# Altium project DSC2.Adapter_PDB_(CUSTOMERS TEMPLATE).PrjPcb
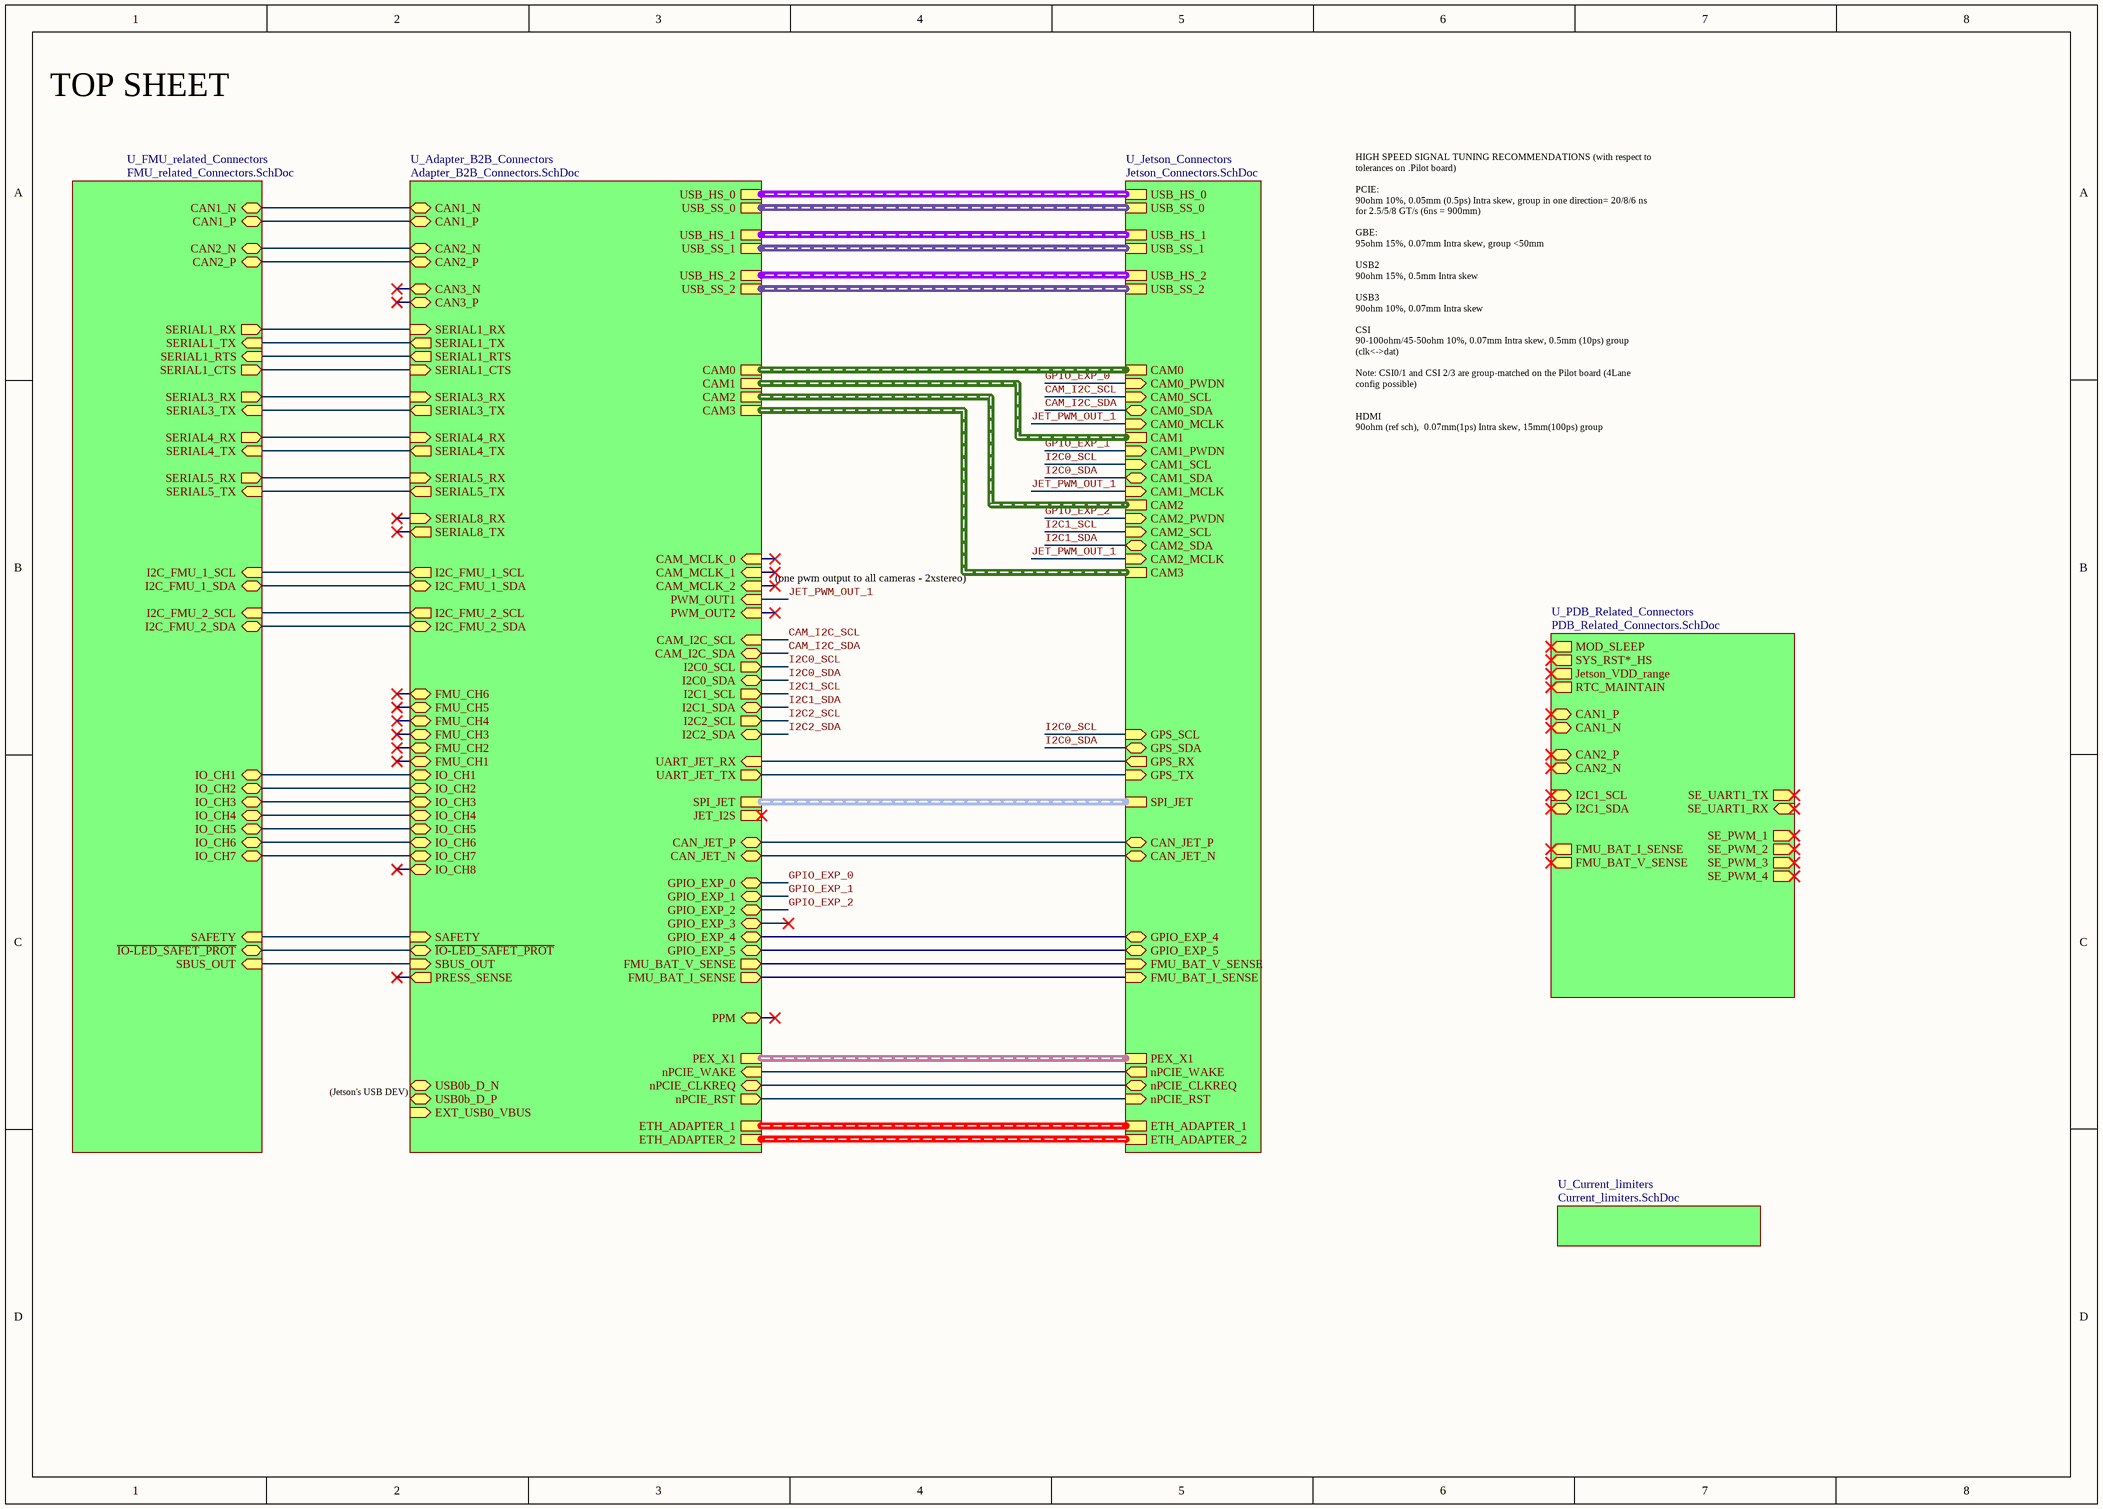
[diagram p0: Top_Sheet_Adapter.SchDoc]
CAGE_CODE: ?????; CONTRACT_NUMBER: <CONTRACT NO>; DOC_NO_ASSY_DWG: <ASSY DWG NO>; DOC_NO_BOM: <BOM DOC NO>; DOC_NO_FAB_DWG: <FAB DWG NO>; DOC_NO_SCH_DWG: <SCH DWG NO>; gDesigner: Ján Parilla; gProjectName: DCS2.Adapter_Template; gRevision: rev.0; gSheetTotal: 3; gYear: 2023; PCB_2_DEC_TOL: +/-.01; PCB_3_DEC_TOL: +/-.010; PCB_ANG_TOL: +/-1/2; PCB_ASSEMBLY_NO: <PCB ASSY NO>; PCB_CHECKER: - -----; PCB_CHECKER_APP_DATE: --/--/----; PCB_DESIGNER: - -----; PCB_DESIGNER_APP_DATE: --/--/----; PCB_DWG_NO: <PCB DWG NO>; PCB_ENGINEER: - -----; PCB_ENGINEER_APP_DATE: --/--/----; PCB_PART_NUMBER: <PCB PN>; PCB_REV: A; SCH_REV: A
7 sheets, 50 parts. Net scope: hierarchical (ports join the sheet entries above them; power ports are global).
Board file: DCS_nano_Adapter_PDB_Template.PcbDoc
Sheets:
  Top_Sheet_Adapter.SchDoc
    U_Adapter_B2B_Connectors = Adapter_B2B_Connectors.SchDoc
    U_Jetson_Connectors = Jetson_Connectors.SchDoc
    U_FMU_related_Connectors = FMU_related_Connectors.SchDoc
    U_PDB_Related_Connectors = PDB_Related_Connectors.SchDoc
    U_Current_limiters = Current_limiters.SchDoc
  DCDC_Regulators.SchDoc

## Sheet Top_Sheet_Adapter.SchDoc
size A3; SheetNumber: 1; SheetTotal: 7

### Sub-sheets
U_Adapter_B2B_Connectors = Adapter_B2B_Connectors.SchDoc: ETH_ADAPTER_1 (harness ETH_GB), CAN_JET_P (bidir), CAN_JET_N (bidir), CAN2_N (bidir), CAN2_P (bidir), CAN1_N (bidir), CAN1_P (bidir), CAN3_N (bidir), CAN3_P (bidir), SERIAL5_RX (in), SERIAL5_TX (out), SERIAL4_RX (in), SERIAL4_TX (out), SERIAL3_RX (in), SERIAL3_TX (out), SERIAL1_TX (out), SERIAL1_RX (in), SERIAL1_CTS (in), SERIAL1_RTS (out), SERIAL8_TX (out), SERIAL8_RX (in), GPIO_EXP_1 (bidir), GPIO_EXP_2 (bidir), GPIO_EXP_0 (bidir), GPIO_EXP_3 (bidir), GPIO_EXP_4 (bidir), GPIO_EXP_5 (bidir), ETH_ADAPTER_2 (harness ETH_GB), I2C_FMU_1_SCL (out), I2C_FMU_1_SDA (bidir), I2C_FMU_2_SCL (out), I2C_FMU_2_SDA (bidir), PRESS_SENSE (out), ~{IO-LED_SAFET_PROT} (bidir), SBUS_OUT (in), SAFETY (in), FMU_CH6 (bidir), FMU_CH5 (bidir), FMU_CH4 (bidir), FMU_CH3 (bidir), FMU_CH2 (bidir), FMU_CH1 (bidir), IO_CH1 (bidir), IO_CH2 (bidir), IO_CH3 (bidir), IO_CH4 (bidir), IO_CH5 (bidir), IO_CH6 (bidir), IO_CH7 (bidir), IO_CH8 (bidir), nPCIE_CLKREQ (bidir), nPCIE_RST (out), nPCIE_WAKE (in), UART_JET_TX (out), UART_JET_RX (in), SPI_JET (harness SPI), PWM_OUT1 (in), PWM_OUT2 (in), CAM0 (harness CSIx2), CAM2 (harness CSIx2), CAM_I2C_SCL (in), CAM_I2C_SDA (bidir), CAM_MCLK_1 (in), CAM_MCLK_2 (in), I2C0_SCL (out), I2C0_SDA (bidir), I2C1_SCL (out), I2C1_SDA (bidir), I2C2_SCL (out), I2C2_SDA (bidir), USB_SS_2 (harness USB3), USB_SS_1 (harness USB3), USB_SS_0 (harness USB3), CAM1 (harness CSIx2), CAM3 (harness CSIx2), CAM_MCLK_0 (in), USB_HS_1 (harness USB2), USB_HS_2 (harness USB2), PEX_X1 (harness PEX_x1), USB_HS_0 (harness USB2), JET_I2S (harness I2S), FMU_BAT_V_SENSE (out), FMU_BAT_I_SENSE (out), PPM (bidir), USB0b_D_N (bidir), USB0b_D_P (bidir), EXT_USB0_VBUS (in)
U_Current_limiters = Current_limiters.SchDoc: no entries
U_FMU_related_Connectors = FMU_related_Connectors.SchDoc: CAN2_N (bidir), CAN2_P (bidir), CAN1_N (bidir), CAN1_P (bidir), SERIAL5_RX (out), SERIAL5_TX (in), SERIAL4_RX (out), SERIAL4_TX (in), SERIAL3_RX (out), SERIAL3_TX (in), SERIAL1_TX (in), SERIAL1_RX (out), SERIAL1_CTS (out), SERIAL1_RTS (in), I2C_FMU_1_SCL (in), I2C_FMU_1_SDA (bidir), I2C_FMU_2_SCL (in), I2C_FMU_2_SDA (bidir), ~{IO-LED_SAFET_PROT} (bidir), SBUS_OUT (in), SAFETY (in), IO_CH1 (bidir), IO_CH2 (bidir), IO_CH3 (bidir), IO_CH4 (bidir), IO_CH5 (bidir), IO_CH6 (bidir), IO_CH7 (bidir)
U_Jetson_Connectors = Jetson_Connectors.SchDoc: CAN_JET_P (bidir), CAN_JET_N (bidir), GPS_TX (in), GPS_RX (out), SPI_JET (harness SPI), CAM0 (harness CSIx2), CAM2 (harness CSIx2), CAM1 (harness CSIx2), CAM3 (harness CSIx2), CAM0_PWDN (in), CAM1_PWDN (in), CAM2_PWDN (in), CAM0_SCL (in), CAM0_SDA (bidir), CAM1_SCL (in), CAM1_SDA (bidir), CAM2_SCL (in), CAM2_SDA (bidir), CAM0_MCLK (in), CAM1_MCLK (in), CAM2_MCLK (in), GPS_SCL (in), GPS_SDA (bidir), ETH_ADAPTER_1 (harness ETH_GB), ETH_ADAPTER_2 (harness ETH_GB), nPCIE_CLKREQ (bidir), nPCIE_RST (in), nPCIE_WAKE (out), PEX_X1 (harness PEX_x1), GPIO_EXP_4 (bidir), GPIO_EXP_5 (bidir), FMU_BAT_V_SENSE (in), FMU_BAT_I_SENSE (in), USB_SS_0 (harness USB3), USB_HS_0 (harness USB2), USB_SS_1 (harness USB3), USB_HS_1 (harness USB2), USB_SS_2 (harness USB3), USB_HS_2 (harness USB2)
U_PDB_Related_Connectors = PDB_Related_Connectors.SchDoc: I2C1_SCL (in), I2C1_SDA (bidir), MOD_SLEEP (out), SYS_RST*_HS (out), Jetson_VDD_range (out), CAN2_P (bidir), CAN2_N (bidir), SE_UART1_TX (out), CAN1_P (bidir), CAN1_N (bidir), SE_UART1_RX (in), SE_PWM_1 (out), SE_PWM_2 (out), SE_PWM_3 (out), SE_PWM_4 (out), RTC_MAINTAIN (out), FMU_BAT_I_SENSE (out), FMU_BAT_V_SENSE (out)

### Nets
CAM_I2C_SCL: sheet U_Adapter_B2B_Connectors/CAM_I2C_SCL, sheet U_Jetson_Connectors/CAM0_SCL
CAM_I2C_SDA: sheet U_Adapter_B2B_Connectors/CAM_I2C_SDA, sheet U_Jetson_Connectors/CAM0_SDA
CAN_1_N: sheet U_Adapter_B2B_Connectors/CAN1_N, sheet U_FMU_related_Connectors/CAN1_N
CAN_1_P: sheet U_Adapter_B2B_Connectors/CAN1_P, sheet U_FMU_related_Connectors/CAN1_P
CAN_2_N: sheet U_Adapter_B2B_Connectors/CAN2_N, sheet U_FMU_related_Connectors/CAN2_N
CAN_2_P: sheet U_Adapter_B2B_Connectors/CAN2_P, sheet U_FMU_related_Connectors/CAN2_P
CAN_JET_N: sheet U_Adapter_B2B_Connectors/CAN_JET_N, sheet U_Jetson_Connectors/CAN_JET_N
CAN_JET_P: sheet U_Adapter_B2B_Connectors/CAN_JET_P, sheet U_Jetson_Connectors/CAN_JET_P
FMU_BAT_I_SENSE: sheet U_Adapter_B2B_Connectors/FMU_BAT_I_SENSE, sheet U_Jetson_Connectors/FMU_BAT_I_SENSE
FMU_BAT_V_SENSE: sheet U_Adapter_B2B_Connectors/FMU_BAT_V_SENSE, sheet U_Jetson_Connectors/FMU_BAT_V_SENSE
FMU_SAFETY_SIG: sheet U_Adapter_B2B_Connectors/SAFETY, sheet U_FMU_related_Connectors/SAFETY
GPIO_EXP_0: sheet U_Adapter_B2B_Connectors/GPIO_EXP_0, sheet U_Jetson_Connectors/CAM0_PWDN
GPIO_EXP_1: sheet U_Adapter_B2B_Connectors/GPIO_EXP_1, sheet U_Jetson_Connectors/CAM1_PWDN
GPIO_EXP_2: sheet U_Adapter_B2B_Connectors/GPIO_EXP_2, sheet U_Jetson_Connectors/CAM2_PWDN
GPIO_EXP_4: sheet U_Adapter_B2B_Connectors/GPIO_EXP_4, sheet U_Jetson_Connectors/GPIO_EXP_4
GPIO_EXP_5: sheet U_Adapter_B2B_Connectors/GPIO_EXP_5, sheet U_Jetson_Connectors/GPIO_EXP_5
I2C0_SCL: sheet U_Adapter_B2B_Connectors/I2C0_SCL, sheet U_Jetson_Connectors/CAM1_SCL, sheet U_Jetson_Connectors/GPS_SCL
I2C0_SDA: sheet U_Adapter_B2B_Connectors/I2C0_SDA, sheet U_Jetson_Connectors/CAM1_SDA, sheet U_Jetson_Connectors/GPS_SDA
I2C1_SCL: sheet U_Adapter_B2B_Connectors/I2C1_SCL, sheet U_Jetson_Connectors/CAM2_SCL
I2C1_SDA: sheet U_Adapter_B2B_Connectors/I2C1_SDA, sheet U_Jetson_Connectors/CAM2_SDA
I2C_FMU_1_SCL: sheet U_Adapter_B2B_Connectors/I2C_FMU_1_SCL, sheet U_FMU_related_Connectors/I2C_FMU_1_SCL
I2C_FMU_1_SDA: sheet U_Adapter_B2B_Connectors/I2C_FMU_1_SDA, sheet U_FMU_related_Connectors/I2C_FMU_1_SDA
I2C_FMU_2_SCL: sheet U_Adapter_B2B_Connectors/I2C_FMU_2_SCL, sheet U_FMU_related_Connectors/I2C_FMU_2_SCL
I2C_FMU_2_SDA: sheet U_Adapter_B2B_Connectors/I2C_FMU_2_SDA, sheet U_FMU_related_Connectors/I2C_FMU_2_SDA
~{IO-LED_SAFET_PROT}: sheet U_Adapter_B2B_Connectors/~{IO-LED_SAFET_PROT}, sheet U_FMU_related_Connectors/~{IO-LED_SAFET_PROT}
IO_CH1: sheet U_Adapter_B2B_Connectors/IO_CH1, sheet U_FMU_related_Connectors/IO_CH1
IO_CH2: sheet U_Adapter_B2B_Connectors/IO_CH2, sheet U_FMU_related_Connectors/IO_CH2
IO_CH3: sheet U_Adapter_B2B_Connectors/IO_CH3, sheet U_FMU_related_Connectors/IO_CH3
IO_CH4: sheet U_Adapter_B2B_Connectors/IO_CH4, sheet U_FMU_related_Connectors/IO_CH4
IO_CH5: sheet U_Adapter_B2B_Connectors/IO_CH5, sheet U_FMU_related_Connectors/IO_CH5
IO_CH6: sheet U_Adapter_B2B_Connectors/IO_CH6, sheet U_FMU_related_Connectors/IO_CH6
IO_CH7: sheet U_Adapter_B2B_Connectors/IO_CH7, sheet U_FMU_related_Connectors/IO_CH7
JET_PWM_OUT_1: sheet U_Adapter_B2B_Connectors/PWM_OUT1, sheet U_Jetson_Connectors/CAM0_MCLK, sheet U_Jetson_Connectors/CAM1_MCLK, sheet U_Jetson_Connectors/CAM2_MCLK
nPCIE_CLKREQ: sheet U_Adapter_B2B_Connectors/nPCIE_CLKREQ, sheet U_Jetson_Connectors/nPCIE_CLKREQ
nPCIE_RST: sheet U_Adapter_B2B_Connectors/nPCIE_RST, sheet U_Jetson_Connectors/nPCIE_RST
nPCIE_WAKE: sheet U_Adapter_B2B_Connectors/nPCIE_WAKE, sheet U_Jetson_Connectors/nPCIE_WAKE
SBUS_OUT: sheet U_Adapter_B2B_Connectors/SBUS_OUT, sheet U_FMU_related_Connectors/SBUS_OUT
SERIAL1_CTS: sheet U_Adapter_B2B_Connectors/SERIAL1_CTS, sheet U_FMU_related_Connectors/SERIAL1_CTS
SERIAL1_RTS: sheet U_Adapter_B2B_Connectors/SERIAL1_RTS, sheet U_FMU_related_Connectors/SERIAL1_RTS
SERIAL1_RX: sheet U_Adapter_B2B_Connectors/SERIAL1_RX, sheet U_FMU_related_Connectors/SERIAL1_RX
SERIAL1_TX: sheet U_Adapter_B2B_Connectors/SERIAL1_TX, sheet U_FMU_related_Connectors/SERIAL1_TX
SERIAL3_RX: sheet U_Adapter_B2B_Connectors/SERIAL3_RX, sheet U_FMU_related_Connectors/SERIAL3_RX
SERIAL3_TX: sheet U_Adapter_B2B_Connectors/SERIAL3_TX, sheet U_FMU_related_Connectors/SERIAL3_TX
SERIAL4_RX: sheet U_Adapter_B2B_Connectors/SERIAL4_RX, sheet U_FMU_related_Connectors/SERIAL4_RX
SERIAL4_TX: sheet U_Adapter_B2B_Connectors/SERIAL4_TX, sheet U_FMU_related_Connectors/SERIAL4_TX
SERIAL5_RX: sheet U_Adapter_B2B_Connectors/SERIAL5_RX, sheet U_FMU_related_Connectors/SERIAL5_RX
SERIAL5_TX: sheet U_Adapter_B2B_Connectors/SERIAL5_TX, sheet U_FMU_related_Connectors/SERIAL5_TX
UART_JET_RX: sheet U_Adapter_B2B_Connectors/UART_JET_RX, sheet U_Jetson_Connectors/GPS_RX
UART_JET_TX: sheet U_Adapter_B2B_Connectors/UART_JET_TX, sheet U_Jetson_Connectors/GPS_TX

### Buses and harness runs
harness sheet U_Adapter_B2B_Connectors/CAM0 = sheet U_Jetson_Connectors/CAM0
harness sheet U_Adapter_B2B_Connectors/CAM1 = sheet U_Jetson_Connectors/CAM1
harness sheet U_Adapter_B2B_Connectors/CAM2 = sheet U_Jetson_Connectors/CAM2
harness sheet U_Adapter_B2B_Connectors/CAM3 = sheet U_Jetson_Connectors/CAM3
harness sheet U_Adapter_B2B_Connectors/ETH_ADAPTER_1 = sheet U_Jetson_Connectors/ETH_ADAPTER_1
harness sheet U_Adapter_B2B_Connectors/ETH_ADAPTER_2 = sheet U_Jetson_Connectors/ETH_ADAPTER_2
harness sheet U_Adapter_B2B_Connectors/PEX_X1 = sheet U_Jetson_Connectors/PEX_X1
harness sheet U_Adapter_B2B_Connectors/SPI_JET = sheet U_Jetson_Connectors/SPI_JET
harness sheet U_Adapter_B2B_Connectors/USB_HS_0 = sheet U_Jetson_Connectors/USB_HS_0
harness sheet U_Adapter_B2B_Connectors/USB_HS_1 = sheet U_Jetson_Connectors/USB_HS_1
harness sheet U_Adapter_B2B_Connectors/USB_HS_2 = sheet U_Jetson_Connectors/USB_HS_2
harness sheet U_Adapter_B2B_Connectors/USB_SS_0 = sheet U_Jetson_Connectors/USB_SS_0
harness sheet U_Adapter_B2B_Connectors/USB_SS_1 = sheet U_Jetson_Connectors/USB_SS_1
harness sheet U_Adapter_B2B_Connectors/USB_SS_2 = sheet U_Jetson_Connectors/USB_SS_2

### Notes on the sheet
- TOP SHEET
- HIGH SPEED SIGNAL TUNING RECOMMENDATIONS (with respect to tolerances on .Pilot board)
  PCIE:
  90ohm 10%, 0.05mm (0.5ps) Intra skew, group in one direction= 20/8/6 ns for 2.5/5/8 GT/s (6ns = 900mm)
  GBE:
  95ohm 15%, 0.07mm Intra skew, group <50mm
  USB2
  90ohm 15%, 0.5mm Intra skew
  USB3
  90ohm 10%, 0.07mm Intra skew
  CSI
  90-100ohm/45-50ohm 10%, 0.07mm Intra skew, 0.5mm (10ps) group (clk<->dat)
  Note: CSI0/1 and CSI 2/3 are group-matched on the Pilot board (4Lane config possible)
  HDMI
  90ohm (ref sch),  0.07mm(1ps) Intra skew, 15mm(100ps) group
- (one pwm output to all cameras - 2xstereo)
- (Jetson's USB DEV)

## Sheet Adapter_B2B_Connectors.SchDoc
size A3; SheetNumber: 2; SheetTotal: 7
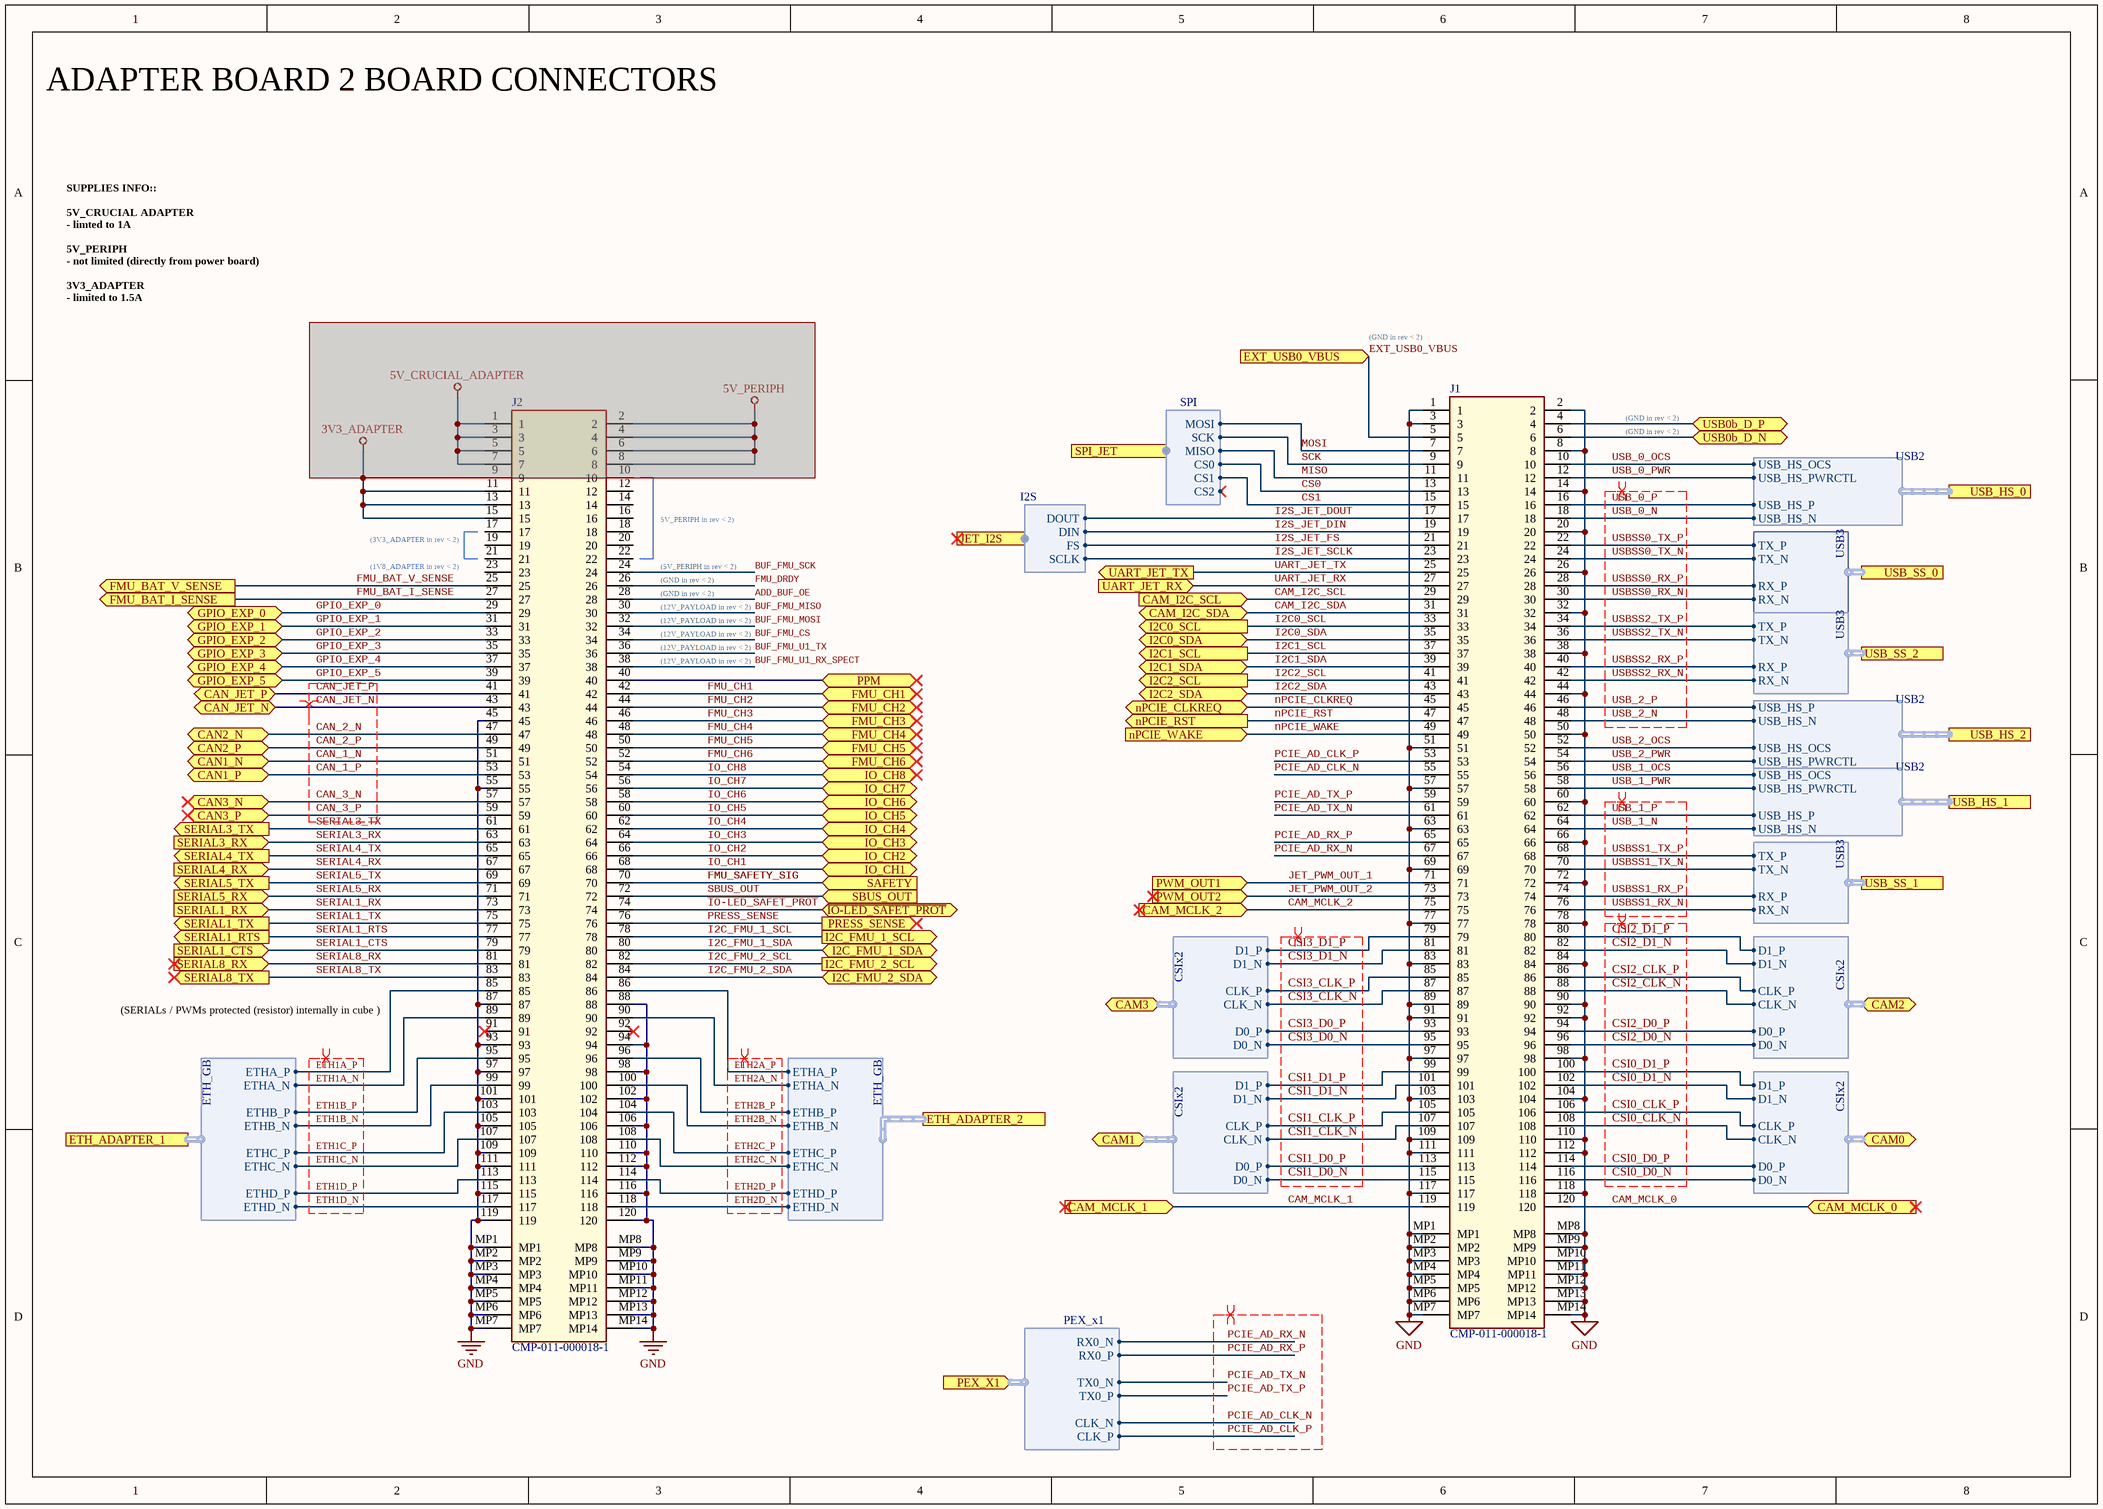
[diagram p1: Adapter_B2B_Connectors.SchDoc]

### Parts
J1  CMP-011-000018-1  [HRS_FX10A-120S/12-SV]
J2  CMP-011-000018-1  [HRS_FX10A-120S/12-SV]

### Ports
CAM0 (bidir, harness CSIx2), CAM1 (bidir, harness CSIx2), CAM2 (bidir, harness CSIx2), CAM3 (bidir, harness CSIx2), CAM_I2C_SCL (in), CAM_I2C_SDA (bidir), CAM_MCLK_0 (in), CAM_MCLK_1 (in), CAM_MCLK_2 (in), CAN1_N (bidir), CAN1_P (bidir), CAN2_N (bidir), CAN2_P (bidir), CAN3_N (bidir), CAN3_P (bidir), CAN_JET_N (bidir), CAN_JET_P (bidir), ETH_ADAPTER_1 (harness ETH_GB), ETH_ADAPTER_2 (harness ETH_GB), EXT_USB0_VBUS (in), FMU_BAT_I_SENSE (out), FMU_BAT_V_SENSE (out), FMU_CH1 (bidir), FMU_CH2 (bidir), FMU_CH3 (bidir), FMU_CH4 (bidir), FMU_CH5 (bidir), FMU_CH6 (bidir), GPIO_EXP_0 (bidir), GPIO_EXP_1 (bidir), GPIO_EXP_2 (bidir), GPIO_EXP_3 (bidir), GPIO_EXP_4 (bidir), GPIO_EXP_5 (bidir), I2C0_SCL (out), I2C0_SDA (bidir), I2C1_SCL (out), I2C1_SDA (bidir), I2C2_SCL (out), I2C2_SDA (bidir), I2C_FMU_1_SCL (out), I2C_FMU_1_SDA (bidir), I2C_FMU_2_SCL (out), I2C_FMU_2_SDA (bidir), IO_CH1 (bidir), IO_CH2 (bidir), IO_CH3 (bidir), IO_CH4 (bidir), IO_CH5 (bidir), IO_CH6 (bidir), IO_CH7 (bidir), IO_CH8 (bidir), JET_I2S (in, harness I2S), nPCIE_CLKREQ (bidir), nPCIE_RST (out), nPCIE_WAKE (in), PEX_X1 (in, harness PEX_x1), PPM (bidir), PRESS_SENSE (out), PWM_OUT1 (in), PWM_OUT2 (in), SAFETY (in), SBUS_OUT (in), SERIAL1_CTS (in), SERIAL1_RTS (out), SERIAL1_RX (in), SERIAL1_TX (out), SERIAL3_RX (in), SERIAL3_TX (out), SERIAL4_RX (in), SERIAL4_TX (out), SERIAL5_RX (in), SERIAL5_TX (out), SERIAL8_RX (in), SERIAL8_TX (out), SPI_JET (harness SPI), UART_JET_RX (in), UART_JET_TX (out), USB0b_D_N (bidir), USB0b_D_P (bidir), USB_HS_0 (harness USB2), USB_HS_1 (harness USB2), USB_HS_2 (harness USB2), USB_SS_0 (harness USB3), USB_SS_1 (harness USB3), USB_SS_2 (harness USB3), ~{IO-LED_SAFET_PROT} (bidir)

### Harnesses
ETH_GB: ETHB_N, ETHB_P, ETHA_P, ETHA_N, ETHD_N, ETHD_P, ETHC_P, ETHC_N
CSIx2: CLK_N, CLK_P, D0_N, D0_P, D1_N, D1_P
SPI: MOSI, MISO, SCK, CS0, CS1, CS2
USB3: RX_N, RX_P, TX_P, TX_N
PEX_x1: CLK_P, CLK_N, TX0_P, TX0_N, RX0_N, RX0_P
USB2: USB_HS_OCS, USB_HS_PWRCTL, USB_HS_P, USB_HS_N
I2S: DOUT, DIN, FS, SCLK

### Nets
GND: J1.1 J1.2 J1.3 J1.8 J1.14 J1.20 J1.26 J1.32 J1.38 J1.44 J1.50 J1.51 J1.57 J1.60 J1.63 J1.66 J1.69 J1.72 J1.77 J1.78 J1.83 J1.84 J1.89 J1.90 J1.91 J1.92 J1.97 J1.98 J1.103 J1.104 J1.109 J1.110 J1.111 J1.112 J1.117 J1.118 J1.MP1 J1.MP2 J1.MP3 J1.MP4 J1.MP5 J1.MP6 J1.MP7 J1.MP8 J1.MP9 J1.MP10 J1.MP11 J1.MP12 J1.MP13 J1.MP14 J2.45 J2.55 J2.87 J2.88 J2.93 J2.94 J2.97 J2.98 J2.101 J2.102 J2.105 J2.106 J2.109 J2.110 J2.111 J2.112 J2.115 J2.116 J2.119 J2.120 J2.MP1 J2.MP2 J2.MP3 J2.MP4 J2.MP5 J2.MP6 J2.MP7 J2.MP8 J2.MP9 J2.MP10 J2.MP11 J2.MP12 J2.MP13 J2.MP14
ADD_BUF_OE: J2.28
BUF_FMU_CS: J2.34
BUF_FMU_MISO: J2.30
BUF_FMU_MOSI: J2.32
BUF_FMU_SCK: J2.24
BUF_FMU_U1_RX_SPECT: J2.38
BUF_FMU_U1_TX: J2.36
CAM_I2C_SCL: J1.29 ; port CAM_I2C_SCL
CAM_I2C_SDA: J1.31 ; port CAM_I2C_SDA
CAM_MCLK_0: J1.120 ; port CAM_MCLK_0
CAM_MCLK_1: J1.119 ; port CAM_MCLK_1
CAM_MCLK_2: J1.75 ; port CAM_MCLK_2
CAN_1_N: J2.51 ; port CAN1_N
CAN_1_P: J2.53 ; port CAN1_P
CAN_2_N: J2.47 ; port CAN2_N
CAN_2_P: J2.49 ; port CAN2_P
CAN_3_N: J2.57 ; port CAN3_N
CAN_3_P: J2.59 ; port CAN3_P
CAN_JET_N: J2.43 ; port CAN_JET_N
CAN_JET_P: J2.41 ; port CAN_JET_P
CS0: J1.13 ; port SPI_JET.CS0
CS1: J1.15 ; port SPI_JET.CS1
CSI0_CLK_N: J1.108 ; port CAM0.CLK_N
CSI0_CLK_P: J1.106 ; port CAM0.CLK_P
CSI0_D0_N: J1.116 ; port CAM0.D0_N
CSI0_D0_P: J1.114 ; port CAM0.D0_P
CSI0_D1_N: J1.102 ; port CAM0.D1_N
CSI0_D1_P: J1.100 ; port CAM0.D1_P
CSI1_CLK_N: J1.107 ; port CAM1.CLK_N
CSI1_CLK_P: J1.105 ; port CAM1.CLK_P
CSI1_D0_N: J1.115 ; port CAM1.D0_N
CSI1_D0_P: J1.113 ; port CAM1.D0_P
CSI1_D1_N: J1.101 ; port CAM1.D1_N
CSI1_D1_P: J1.99 ; port CAM1.D1_P
CSI2_CLK_N: J1.88 ; port CAM2.CLK_N
CSI2_CLK_P: J1.86 ; port CAM2.CLK_P
CSI2_D0_N: J1.96 ; port CAM2.D0_N
CSI2_D0_P: J1.94 ; port CAM2.D0_P
CSI2_D1_N: J1.82 ; port CAM2.D1_N
CSI2_D1_P: J1.80 ; port CAM2.D1_P
CSI3_CLK_N: J1.87 ; port CAM3.CLK_N
CSI3_CLK_P: J1.85 ; port CAM3.CLK_P
CSI3_D0_N: J1.95 ; port CAM3.D0_N
CSI3_D0_P: J1.93 ; port CAM3.D0_P
CSI3_D1_N: J1.81 ; port CAM3.D1_N
CSI3_D1_P: J1.79 ; port CAM3.D1_P
ETH1A_N: J2.89 ; port ETH_ADAPTER_1.ETHA_N
ETH1A_P: J2.85 ; port ETH_ADAPTER_1.ETHA_P
ETH1B_N: J2.99 ; port ETH_ADAPTER_1.ETHB_N
ETH1B_P: J2.95 ; port ETH_ADAPTER_1.ETHB_P
ETH1C_N: J2.107 ; port ETH_ADAPTER_1.ETHC_N
ETH1C_P: J2.103 ; port ETH_ADAPTER_1.ETHC_P
ETH1D_N: J2.117 ; port ETH_ADAPTER_1.ETHD_N
ETH1D_P: J2.113 ; port ETH_ADAPTER_1.ETHD_P
ETH2A_N: J2.90 ; port ETH_ADAPTER_2.ETHA_N
ETH2A_P: J2.86 ; port ETH_ADAPTER_2.ETHA_P
ETH2B_N: J2.100 ; port ETH_ADAPTER_2.ETHB_N
ETH2B_P: J2.96 ; port ETH_ADAPTER_2.ETHB_P
ETH2C_N: J2.108 ; port ETH_ADAPTER_2.ETHC_N
ETH2C_P: J2.104 ; port ETH_ADAPTER_2.ETHC_P
ETH2D_N: J2.118 ; port ETH_ADAPTER_2.ETHD_N
ETH2D_P: J2.114 ; port ETH_ADAPTER_2.ETHD_P
EXT_USB0_VBUS: J1.5 ; port EXT_USB0_VBUS
FMU_BAT_I_SENSE: J2.27 ; port FMU_BAT_I_SENSE
FMU_BAT_V_SENSE: J2.25 ; port FMU_BAT_V_SENSE
FMU_CH1: J2.42 ; port FMU_CH1
FMU_CH2: J2.44 ; port FMU_CH2
FMU_CH3: J2.46 ; port FMU_CH3
FMU_CH4: J2.48 ; port FMU_CH4
FMU_CH5: J2.50 ; port FMU_CH5
FMU_CH6: J2.52 ; port FMU_CH6
FMU_DRDY: J2.26
FMU_SAFETY_SIG: J2.70 ; port SAFETY
GPIO_EXP_0: J2.29 ; port GPIO_EXP_0
GPIO_EXP_1: J2.31 ; port GPIO_EXP_1
GPIO_EXP_2: J2.33 ; port GPIO_EXP_2
GPIO_EXP_3: J2.35 ; port GPIO_EXP_3
GPIO_EXP_4: J2.37 ; port GPIO_EXP_4
GPIO_EXP_5: J2.39 ; port GPIO_EXP_5
I2C0_SCL: J1.33 ; port I2C0_SCL
I2C0_SDA: J1.35 ; port I2C0_SDA
I2C1_SCL: J1.37 ; port I2C1_SCL
I2C1_SDA: J1.39 ; port I2C1_SDA
I2C2_SCL: J1.41 ; port I2C2_SCL
I2C2_SDA: J1.43 ; port I2C2_SDA
I2C_FMU_1_SCL: J2.78 ; port I2C_FMU_1_SCL
I2C_FMU_1_SDA: J2.80 ; port I2C_FMU_1_SDA
I2C_FMU_2_SCL: J2.82 ; port I2C_FMU_2_SCL
I2C_FMU_2_SDA: J2.84 ; port I2C_FMU_2_SDA
I2S_JET_DIN: J1.19 ; port JET_I2S.DIN
I2S_JET_DOUT: J1.17 ; port JET_I2S.DOUT
I2S_JET_FS: J1.21 ; port JET_I2S.FS
I2S_JET_SCLK: J1.23 ; port JET_I2S.SCLK
~{IO-LED_SAFET_PROT}: J2.74 ; port ~{IO-LED_SAFET_PROT}
IO_CH1: J2.68 ; port IO_CH1
IO_CH2: J2.66 ; port IO_CH2
IO_CH3: J2.64 ; port IO_CH3
IO_CH4: J2.62 ; port IO_CH4
IO_CH5: J2.60 ; port IO_CH5
IO_CH6: J2.58 ; port IO_CH6
IO_CH7: J2.56 ; port IO_CH7
IO_CH8: J2.54 ; port IO_CH8
JET_PWM_OUT_1: J1.71 ; port PWM_OUT1
JET_PWM_OUT_2: J1.73 ; port PWM_OUT2
MISO: J1.11 ; port SPI_JET.MISO
MOSI: J1.7 ; port SPI_JET.MOSI
nPCIE_CLKREQ: J1.45 ; port nPCIE_CLKREQ
nPCIE_RST: J1.47 ; port nPCIE_RST
nPCIE_WAKE: J1.49 ; port nPCIE_WAKE
PCIE_AD_CLK_N: J1.55 ; port PEX_X1.CLK_N
PCIE_AD_CLK_P: J1.53 ; port PEX_X1.CLK_P
PCIE_AD_RX_N: J1.67 ; port PEX_X1.RX0_N
PCIE_AD_RX_P: J1.65 ; port PEX_X1.RX0_P
PCIE_AD_TX_N: J1.61 ; port PEX_X1.TX0_N
PCIE_AD_TX_P: J1.59 ; port PEX_X1.TX0_P
PRESS_SENSE: J2.76 ; port PRESS_SENSE
SBUS_OUT: J2.72 ; port SBUS_OUT
SCK: J1.9 ; port SPI_JET.SCK
SERIAL1_CTS: J2.79 ; port SERIAL1_CTS
SERIAL1_RTS: J2.77 ; port SERIAL1_RTS
SERIAL1_RX: J2.73 ; port SERIAL1_RX
SERIAL1_TX: J2.75 ; port SERIAL1_TX
SERIAL3_RX: J2.63 ; port SERIAL3_RX
SERIAL3_TX: J2.61 ; port SERIAL3_TX
SERIAL4_RX: J2.67 ; port SERIAL4_RX
SERIAL4_TX: J2.65 ; port SERIAL4_TX
SERIAL5_RX: J2.71 ; port SERIAL5_RX
SERIAL5_TX: J2.69 ; port SERIAL5_TX
SERIAL8_RX: J2.81 ; port SERIAL8_RX
SERIAL8_TX: J2.83 ; port SERIAL8_TX
UART_JET_RX: J1.27 ; port UART_JET_RX
UART_JET_TX: J1.25 ; port UART_JET_TX
USB_0_N: J1.18 ; port USB_HS_0.USB_HS_N
USB_0_OCS: J1.10 ; port USB_HS_0.USB_HS_OCS
USB_0_P: J1.16 ; port USB_HS_0.USB_HS_P
USB_0_PWR: J1.12 ; port USB_HS_0.USB_HS_PWRCTL
USB_1_N: J1.64 ; port USB_HS_1.USB_HS_N
USB_1_OCS: J1.56 ; port USB_HS_1.USB_HS_OCS
USB_1_P: J1.62 ; port USB_HS_1.USB_HS_P
USB_1_PWR: J1.58 ; port USB_HS_1.USB_HS_PWRCTL
USB_2_N: J1.48 ; port USB_HS_2.USB_HS_N
USB_2_OCS: J1.52 ; port USB_HS_2.USB_HS_OCS
USB_2_P: J1.46 ; port USB_HS_2.USB_HS_P
USB_2_PWR: J1.54 ; port USB_HS_2.USB_HS_PWRCTL
USBSS0_RX_N: J1.30 ; port USB_SS_0.RX_N
USBSS0_RX_P: J1.28 ; port USB_SS_0.RX_P
USBSS0_TX_N: J1.24 ; port USB_SS_0.TX_N
USBSS0_TX_P: J1.22 ; port USB_SS_0.TX_P
USBSS1_RX_N: J1.76 ; port USB_SS_1.RX_N
USBSS1_RX_P: J1.74 ; port USB_SS_1.RX_P
USBSS1_TX_N: J1.70 ; port USB_SS_1.TX_N
USBSS1_TX_P: J1.68 ; port USB_SS_1.TX_P
USBSS2_RX_N: J1.42 ; port USB_SS_2.RX_N
USBSS2_RX_P: J1.40 ; port USB_SS_2.RX_P
USBSS2_TX_N: J1.36 ; port USB_SS_2.TX_N
USBSS2_TX_P: J1.34 ; port USB_SS_2.TX_P
NetJ1_4: J1.4 ; port USB0b_D_P
NetJ1_6: J1.6 ; port USB0b_D_N
NetJ2_11: J2.11 J2.13 J2.15
NetJ2_40: J2.40 ; port PPM

Not connected (* = marked no-connect by the designer): J2 1 2 3 4 5 6 7 8 9 10 12 14 16 17 18 19 20 21 22 23 91* 92*

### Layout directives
differential pair; net class ETH_NETS; differential pair class 95OHM_NETS: ETH1A_N, ETH1A_P, ETH1B_N, ETH1B_P, ETH1C_N, ETH1C_P, ETH1D_N, ETH1D_P, ETH2A_P
differential pair; net class USB_NETS; differential pair class 90OHM_NETS: USB_0_N, USB_0_P, USB_1_N, USB_1_P, USB_2_N, USB_2_P, USBSS0_RX_N, USBSS0_RX_P, USBSS0_TX_N, USBSS0_TX_P, USBSS1_RX_N, USBSS1_RX_P, USBSS1_TX_N, USBSS1_TX_P, USBSS2_RX_N, USBSS2_RX_P, USBSS2_TX_N, USBSS2_TX_P
differential pair; net class PCIE_NETS; differential pair class 90OHM_NETS: PCIE_AD_CLK_N, PCIE_AD_CLK_P, PCIE_AD_RX_N, PCIE_AD_RX_P, PCIE_AD_TX_N, PCIE_AD_TX_P
differential pair; net class CSI_NETS; differential pair class 90OHM_NETS: CSI0_CLK_N, CSI0_CLK_P, CSI0_D0_N, CSI0_D0_P, CSI0_D1_N, CSI0_D1_P, CSI1_CLK_N, CSI1_CLK_P, CSI1_D0_N, CSI1_D0_P, CSI1_D1_N, CSI1_D1_P, CSI2_CLK_N, CSI2_CLK_P, CSI2_D0_N, CSI2_D0_P, CSI2_D1_N, CSI2_D1_P, CSI3_CLK_N, CSI3_CLK_P, CSI3_D0_N, CSI3_D0_P, CSI3_D1_N, CSI3_D1_P
differential pair; net class CAN_NETS: CAN_1_N, CAN_1_P, CAN_2_N, CAN_2_P, CAN_3_N, CAN_3_P, CAN_JET_N, CAN_JET_P

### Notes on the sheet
- ADAPTER BOARD 2 BOARD CONNECTORS
- SUPPLIES INFO::
  5V_CRUCIAL ADAPTER
  - limted to 1A
  5V_PERIPH
  - not limited (directly from power board)
  3V3_ADAPTER
  - limited to 1.5A
- (GND in rev < 2)
- (3V3_ADAPTER in rev < 2)
- (1V8_ADAPTER in rev < 2)
- 5V_PERIPH in rev < 2)
- (5V_PERIPH in rev < 2)
- (12V_PAYLOAD in rev < 2)
- (SERIALs / PWMs protected (resistor) internally in cube )

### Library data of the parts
J1 J2 = CMP-011-000018-1: 120 Position Connector Receptacle, Center Strip Contacts Surface Mount Gold; Manufacturer_Name: Hirose Electric Co Ltd

## Sheet Jetson_Connectors.SchDoc
size A3; SheetNumber: 4; SheetTotal: 7
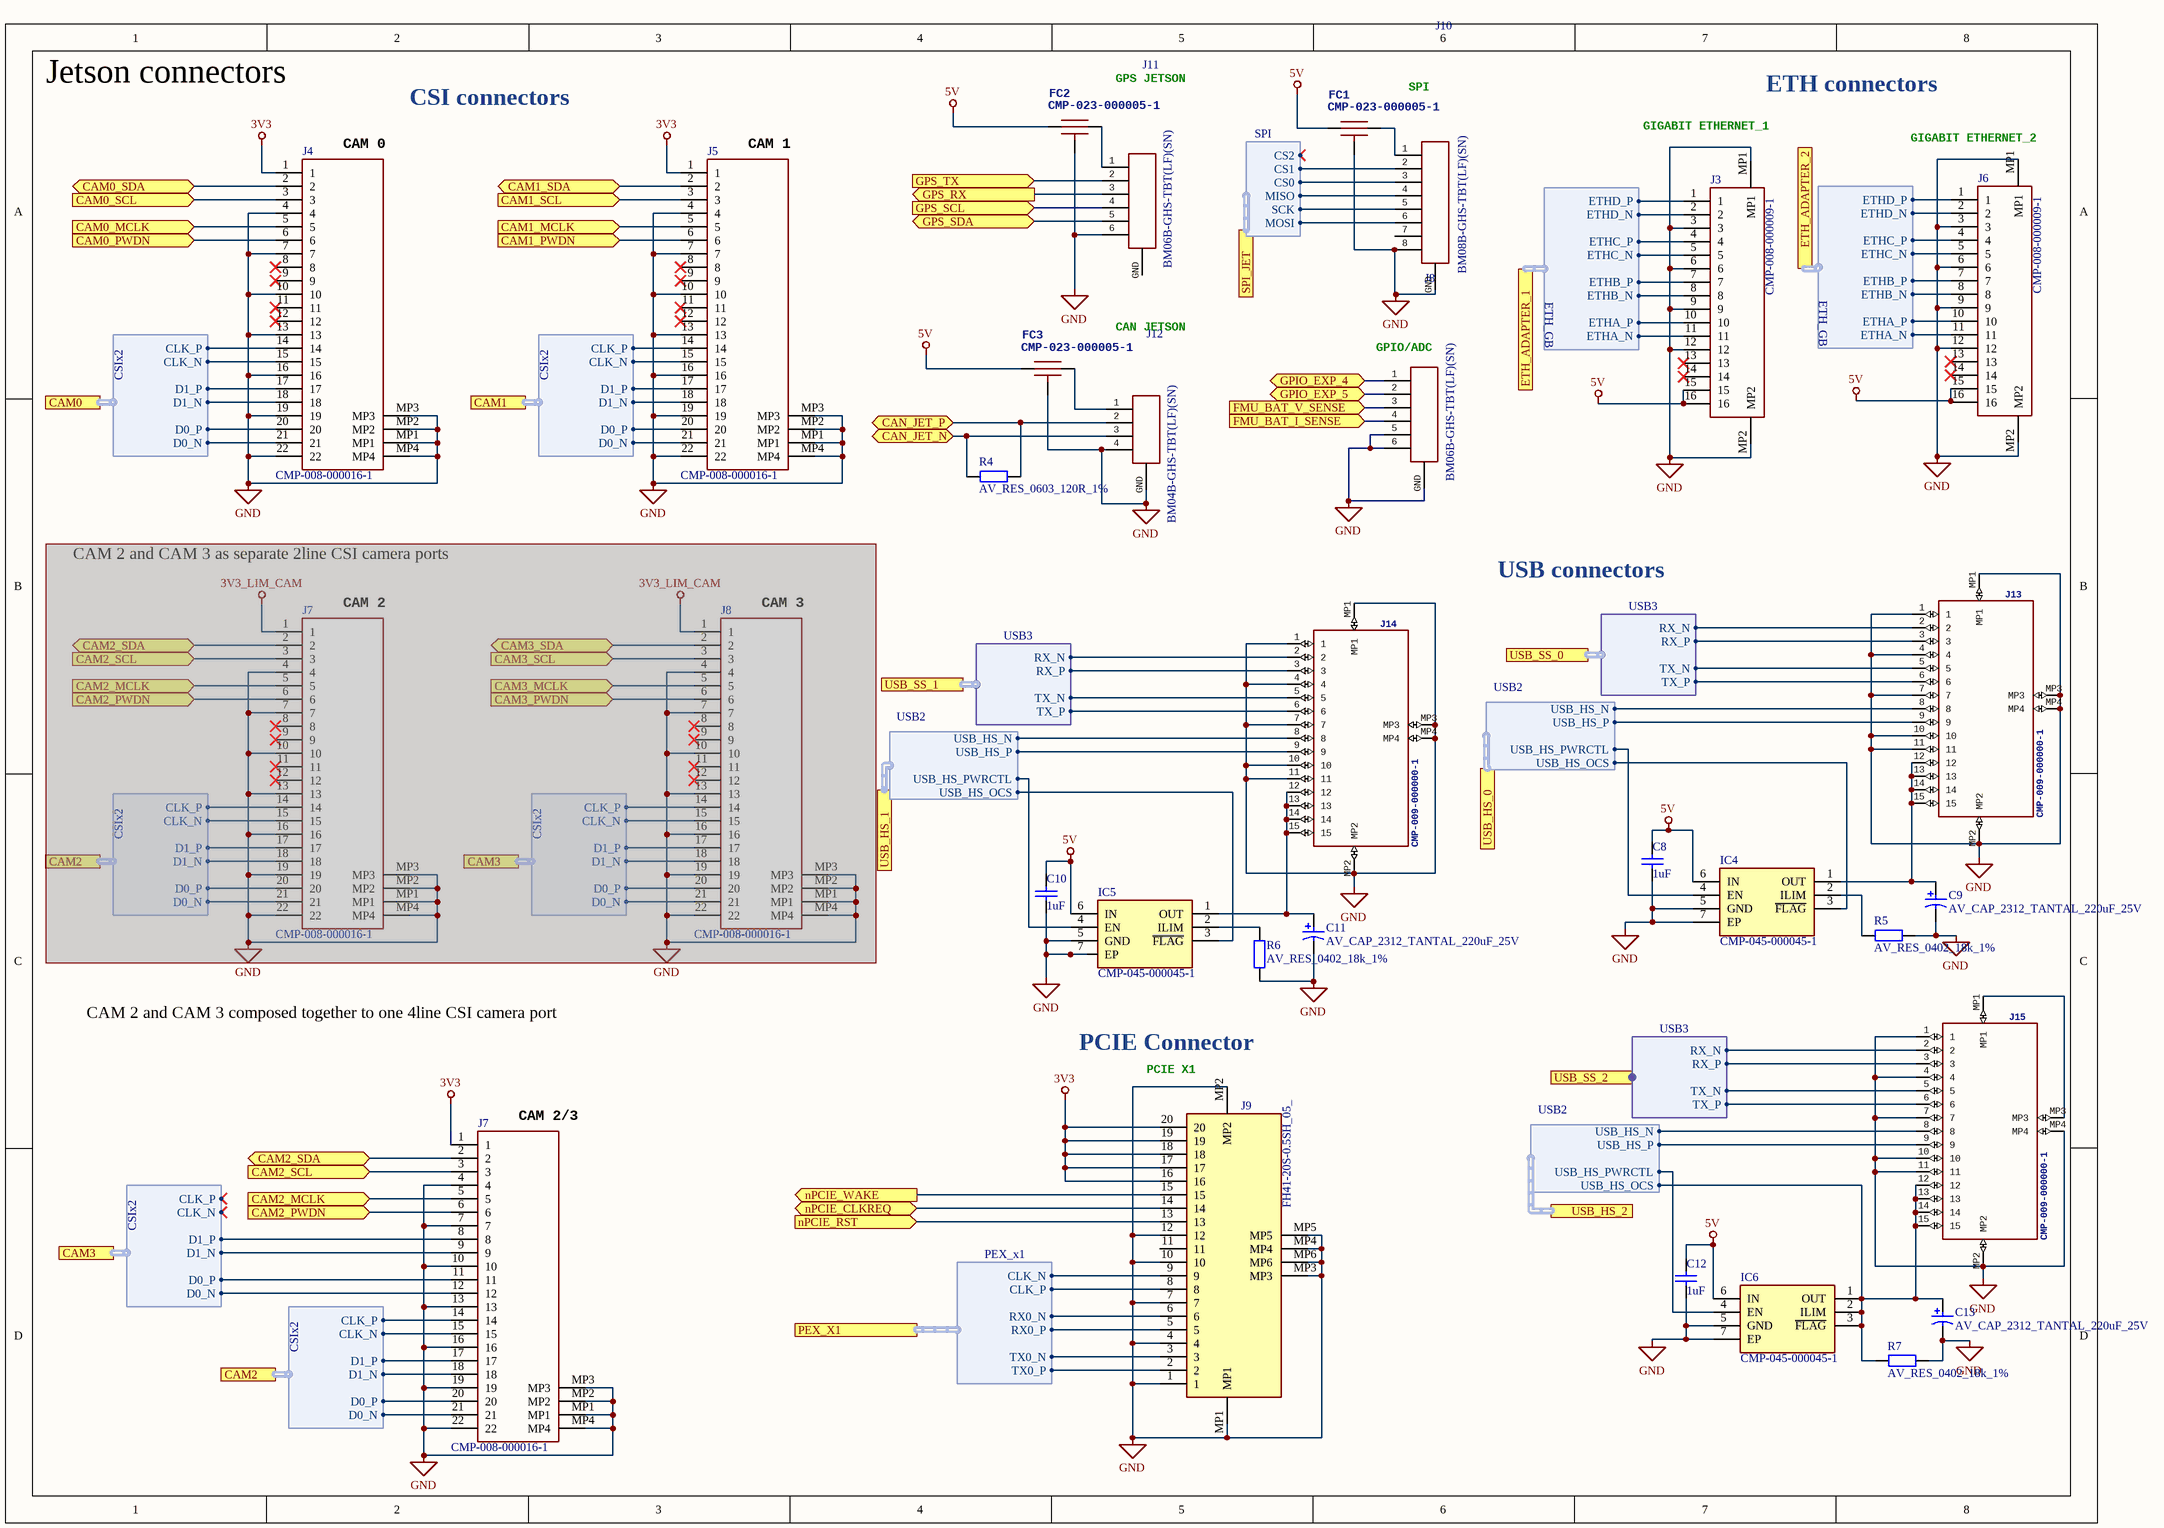
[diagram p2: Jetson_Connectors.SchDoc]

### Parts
(Parts that share a designator on the sheet are numbered #1, #2 ... from top to bottom, then left to right.)
C8  value 1uF  [C0402]  (hidden comment: AV_CAP_0402_1uF_25V)
C9  AV_CAP_2312_TANTAL_220uF_25V  [AVX-TAJ-C-2_L]
C10  value 1uF  [C0402]  (hidden comment: AV_CAP_0402_1uF_25V)
C11  AV_CAP_2312_TANTAL_220uF_25V  [AVX-TAJ-C-2_L]
C12  value 1uF  [C0402]  (hidden comment: AV_CAP_0402_1uF_25V)
C13  AV_CAP_2312_TANTAL_220uF_25V  [AVX-TAJ-C-2_L]
FC1  CMP-023-000005-1  [NFM18PS105R0J3D]
FC2  CMP-023-000005-1  [NFM18PS105R0J3D]
FC3  CMP-023-000005-1  [NFM18PS105R0J3D]
IC4  CMP-045-000045-1  [SON65P200X200X55-7N]
IC5  CMP-045-000045-1  [SON65P200X200X55-7N]
IC6  CMP-045-000045-1  [SON65P200X200X55-7N]
J3  CMP-008-000009-1  [5051101692]
J4  CMP-008-000016-1  [5019512210]
J5  CMP-008-000016-1  [5019512210]
J6  CMP-008-000009-1  [5051101692]
J7#1  CMP-008-000016-1  [5019512210]  (masked out: inside a compile mask, not in the netlist)
J7#2  CMP-008-000016-1  [5019512210]
J8#1  BM06B-GHS-TBT(LF)(SN)  [FP-BM06B-GHS-TBT_LF_SN-MFG]
J8#2  CMP-008-000016-1  [5019512210]  (masked out: inside a compile mask, not in the netlist)
J9  FH41-20S-0.5SH_05_  [FH4120S05SH05]
J10  BM08B-GHS-TBT(LF)(SN)  [FP-BM08B-GHS-TBT_LF_SN-MFG]
J11  BM06B-GHS-TBT(LF)(SN)  [FP-BM06B-GHS-TBT_LF_SN-MFG]
J12  BM04B-GHS-TBT(LF)(SN)  [FP-BM04B-GHS-TBT_LF_SN-MFG]
J13  CMP-009-000000-1  [5022441530]
J14  CMP-009-000000-1  [5022441530]
J15  CMP-009-000000-1  [5022441530]
R4  AV_RES_0603_120R_1%  [R0603]
R5  AV_RES_0402_18k_1%  [R0402]
R6  AV_RES_0402_18k_1%  [R0402]
R7  AV_RES_0402_18k_1%  [R0402]

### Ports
CAM0 (harness CSIx2), CAM0_MCLK (in), CAM0_PWDN (in), CAM0_SCL (in), CAM0_SDA (bidir), CAM1 (harness CSIx2), CAM1_MCLK (in), CAM1_PWDN (in), CAM1_SCL (in), CAM1_SDA (bidir), CAM2 (harness CSIx2), CAM2_MCLK (in), CAM2_PWDN (in), CAM2_SCL (in), CAM2_SDA (bidir), CAM3 (harness CSIx2), CAM3_MCLK (in), CAM3_PWDN (in), CAM3_SCL (in), CAM3_SDA (bidir), CAN_JET_N (bidir), CAN_JET_P (bidir), ETH_ADAPTER_1 (harness ETH_GB), ETH_ADAPTER_2 (harness ETH_GB), FMU_BAT_I_SENSE (in), FMU_BAT_V_SENSE (in), GPIO_EXP_4 (bidir), GPIO_EXP_5 (bidir), GPS_RX (out), GPS_SCL (in), GPS_SDA (bidir), GPS_TX (in), nPCIE_CLKREQ (bidir), nPCIE_RST (in), nPCIE_WAKE (out), PEX_X1 (harness PEX_x1), SPI_JET (harness SPI), USB_HS_0 (harness USB2), USB_HS_1 (harness USB2), USB_HS_2 (harness USB2), USB_SS_0 (harness USB3), USB_SS_1 (harness USB3), USB_SS_2 (harness USB3)

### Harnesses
CSIx2: CLK_N, CLK_P, D0_N, D0_P, D1_N, D1_P
ETH_GB: ETHB_N, ETHB_P, ETHA_P, ETHA_N, ETHD_N, ETHD_P, ETHC_P, ETHC_N
PEX_x1: CLK_P, CLK_N, TX0_P, TX0_N, RX0_N, RX0_P
SPI: MOSI, MISO, SCK, CS0, CS1, CS2
USB3: RX_N, RX_P, TX_P, TX_N
USB2: USB_HS_OCS, USB_HS_PWRCTL, USB_HS_P, USB_HS_N

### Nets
3V3: J4.1 J5.1 J7#2.1 J9.16 J9.17 J9.18 J9.19 J9.20
5V: C8.1 C10.1 C12.1 FC1.1 FC2.1 FC3.1 IC4.6(IN) IC5.6(IN) IC6.6(IN) J3.15 J3.16 J6.15 J6.16
GND: C8.2 C9.- C10.2 C11.- C12.2 C13.- FC1.GND FC2.GND FC3.GND IC4.5(GND) IC4.7(EP) IC5.5(GND) IC5.7(EP) IC6.5(GND) IC6.7(EP) J3.3 J3.6 J3.9 J3.12 J3.MP1 J3.MP2 J4.4 J4.7 J4.10 J4.13 J4.16 J4.19 J4.22 J4.MP1 J4.MP2 J4.MP3 J4.MP4 J5.4 J5.7 J5.10 J5.13 J5.16 J5.19 J5.22 J5.MP1 J5.MP2 J5.MP3 J5.MP4 J6.3 J6.6 J6.9 J6.12 J6.MP1 J6.MP2 J7#2.4 J7#2.7 J7#2.10 J7#2.13 J7#2.16 J7#2.19 J7#2.22 J7#2.MP1 J7#2.MP2 J7#2.MP3 J7#2.MP4 J8#1.5 J8#1.6 J8#1.GND J9.1 J9.4 J9.7 J9.10 J9.12 J9.MP1 J9.MP2 J9.MP3 J9.MP4 J9.MP5 J9.MP6 J10.8 J10.GND J11.6 J12.4 J12.GND J13.1 J13.4 J13.7 J13.10 J13.11 J13.MP1 J13.MP2 J13.MP3 J13.MP4 J14.1 J14.4 J14.7 J14.10 J14.11 J14.MP1 J14.MP2 J14.MP3 J14.MP4 J15.1 J15.4 J15.7 J15.10 J15.11 J15.MP2 J15.MP4 R5.1 R6.1 R7.1
CAM_I2C_SCL: J4.3 ; port CAM0_SCL
CAM_I2C_SDA: J4.2 ; port CAM0_SDA
CAN_JET_N: J12.3 R4.1 ; port CAN_JET_N
CAN_JET_P: J12.2 R4.2 ; port CAN_JET_P
CS0: J10.3 ; port SPI_JET.CS0
CS1: J10.2 ; port SPI_JET.CS1
CSI0_CLK_N: J4.15 ; port CAM0.CLK_N
CSI0_CLK_P: J4.14 ; port CAM0.CLK_P
CSI0_D0_N: J4.21 ; port CAM0.D0_N
CSI0_D0_P: J4.20 ; port CAM0.D0_P
CSI0_D1_N: J4.18 ; port CAM0.D1_N
CSI0_D1_P: J4.17 ; port CAM0.D1_P
CSI1_CLK_N: J5.15 ; port CAM1.CLK_N
CSI1_CLK_P: J5.14 ; port CAM1.CLK_P
CSI1_D0_N: J5.21 ; port CAM1.D0_N
CSI1_D0_P: J5.20 ; port CAM1.D0_P
CSI1_D1_N: J5.18 ; port CAM1.D1_N
CSI1_D1_P: J5.17 ; port CAM1.D1_P
CSI2_CLK_N: J7#2.15 ; port CAM2.CLK_N
CSI2_CLK_P: J7#2.14 ; port CAM2.CLK_P
CSI2_D0_N: J7#2.21 ; port CAM2.D0_N
CSI2_D0_P: J7#2.20 ; port CAM2.D0_P
CSI2_D1_N: J7#2.18 ; port CAM2.D1_N
CSI2_D1_P: J7#2.17 ; port CAM2.D1_P
CSI3_D0_N: J7#2.12 ; port CAM3.D0_N
CSI3_D0_P: J7#2.11 ; port CAM3.D0_P
CSI3_D1_N: J7#2.9 ; port CAM3.D1_N
CSI3_D1_P: J7#2.8 ; port CAM3.D1_P
ETH1A_N: J3.11 ; port ETH_ADAPTER_1.ETHA_N
ETH1A_P: J3.10 ; port ETH_ADAPTER_1.ETHA_P
ETH1B_N: J3.8 ; port ETH_ADAPTER_1.ETHB_N
ETH1B_P: J3.7 ; port ETH_ADAPTER_1.ETHB_P
ETH1C_N: J3.5 ; port ETH_ADAPTER_1.ETHC_N
ETH1C_P: J3.4 ; port ETH_ADAPTER_1.ETHC_P
ETH1D_N: J3.2 ; port ETH_ADAPTER_1.ETHD_N
ETH1D_P: J3.1 ; port ETH_ADAPTER_1.ETHD_P
ETH2A_N: J6.11 ; port ETH_ADAPTER_2.ETHA_N
ETH2A_P: J6.10 ; port ETH_ADAPTER_2.ETHA_P
ETH2B_N: J6.8 ; port ETH_ADAPTER_2.ETHB_N
ETH2B_P: J6.7 ; port ETH_ADAPTER_2.ETHB_P
ETH2C_N: J6.5 ; port ETH_ADAPTER_2.ETHC_N
ETH2C_P: J6.4 ; port ETH_ADAPTER_2.ETHC_P
ETH2D_N: J6.2 ; port ETH_ADAPTER_2.ETHD_N
ETH2D_P: J6.1 ; port ETH_ADAPTER_2.ETHD_P
FMU_BAT_I_SENSE: J8#1.4 ; port FMU_BAT_I_SENSE
FMU_BAT_V_SENSE: J8#1.3 ; port FMU_BAT_V_SENSE
GPIO_EXP_0: J4.6 ; port CAM0_PWDN
GPIO_EXP_1: J5.6 ; port CAM1_PWDN
GPIO_EXP_2: J7#2.6 ; port CAM2_PWDN
GPIO_EXP_4: J8#1.1 ; port GPIO_EXP_4
GPIO_EXP_5: J8#1.2 ; port GPIO_EXP_5
I2C0_SCL: J5.3 J11.4 ; port CAM1_SCL, port GPS_SCL
I2C0_SDA: J5.2 J11.5 ; port CAM1_SDA, port GPS_SDA
I2C1_SCL: J7#2.3 ; port CAM2_SCL
I2C1_SDA: J7#2.2 ; port CAM2_SDA
JET_PWM_OUT_1: J4.5 J5.5 J7#2.5 ; port CAM0_MCLK, port CAM1_MCLK, port CAM2_MCLK
MISO: J10.4 ; port SPI_JET.MISO
MOSI: J10.6 ; port SPI_JET.MOSI
nPCIE_CLKREQ: J9.14 ; port nPCIE_CLKREQ
nPCIE_RST: J9.13 ; port nPCIE_RST
nPCIE_WAKE: J9.15 ; port nPCIE_WAKE
PCIE_AD_CLK_N: J9.9 ; port PEX_X1.CLK_N
PCIE_AD_CLK_P: J9.8 ; port PEX_X1.CLK_P
PCIE_AD_RX_N: J9.6 ; port PEX_X1.RX0_N
PCIE_AD_RX_P: J9.5 ; port PEX_X1.RX0_P
PCIE_AD_TX_N: J9.3 ; port PEX_X1.TX0_N
PCIE_AD_TX_P: J9.2 ; port PEX_X1.TX0_P
SCK: J10.5 ; port SPI_JET.SCK
UART_JET_RX: J11.3 ; port GPS_RX
UART_JET_TX: J11.2 ; port GPS_TX
USB_0_N: J13.8 ; port USB_HS_0.USB_HS_N
USB_0_OCS: IC4.3(~{FLAG}) ; port USB_HS_0.USB_HS_OCS
USB_0_P: J13.9 ; port USB_HS_0.USB_HS_P
USB_0_PWR: IC4.4(EN) ; port USB_HS_0.USB_HS_PWRCTL
USB_1_N: J14.8 ; port USB_HS_1.USB_HS_N
USB_1_OCS: IC5.3(~{FLAG}) ; port USB_HS_1.USB_HS_OCS
USB_1_P: J14.9 ; port USB_HS_1.USB_HS_P
USB_1_PWR: IC5.4(EN) ; port USB_HS_1.USB_HS_PWRCTL
USB_2_N: J15.8 ; port USB_HS_2.USB_HS_N
USB_2_OCS: C13.+ IC6.1(OUT) IC6.2(ILIM) IC6.3(~{FLAG}) J15.12 J15.13 J15.14 J15.15 R7.2 ; port USB_HS_2.USB_HS_OCS
USB_2_P: J15.9 ; port USB_HS_2.USB_HS_P
USB_2_PWR: IC6.4(EN) ; port USB_HS_2.USB_HS_PWRCTL
USBSS0_RX_N: J13.2 ; port USB_SS_0.RX_N
USBSS0_RX_P: J13.3 ; port USB_SS_0.RX_P
USBSS0_TX_N: J13.5 ; port USB_SS_0.TX_N
USBSS0_TX_P: J13.6 ; port USB_SS_0.TX_P
USBSS1_RX_N: J14.2 ; port USB_SS_1.RX_N
USBSS1_RX_P: J14.3 ; port USB_SS_1.RX_P
USBSS1_TX_N: J14.5 ; port USB_SS_1.TX_N
USBSS1_TX_P: J14.6 ; port USB_SS_1.TX_P
USBSS2_RX_N: J15.2 ; port USB_SS_2.RX_N
USBSS2_RX_P: J15.3 ; port USB_SS_2.RX_P
USBSS2_TX_N: J15.5 ; port USB_SS_2.TX_N
USBSS2_TX_P: J15.6 ; port USB_SS_2.TX_P
NetC9_+: C9.+ IC4.1(OUT) J13.12 J13.13 J13.14 J13.15
NetC11_+: C11.+ IC5.1(OUT) J14.12 J14.13 J14.14 J14.15
NetFC1_2: FC1.2 J10.1
NetFC2_2: FC2.2 J11.1
NetFC3_2: FC3.2 J12.1
NetIC4_2: IC4.2(ILIM) R5.2
NetIC5_2: IC5.2(ILIM) R6.2
NetJ15_MP1: J15.MP1 J15.MP3

Not connected (* = marked no-connect by the designer): J3 13* 14*; J4 8* 9* 11* 12*; J5 8* 9* 11* 12*; J6 13* 14*; J9 11; J10 7; J11 GND

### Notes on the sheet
- Jetson connectors
- CSI connectors
- (near FC2) GPS JETSON
- SPI
- GIGABIT ETHERNET_1
- ETH connectors
- (near J4) CAM 0
- (near J5) CAM 1
- (near J6) GIGABIT ETHERNET_2
- CAN JETSON
- (near J8#1) GPIO/ADC
- CAM 2 and CAM 3 as separate 2line CSI camera ports
- (near J7#1) CAM 2
- (near J8#2) CAM 3
- USB connectors
- CAM 2 and CAM 3 composed together to one 4line CSI camera port
- PCIE Connector
- (near J9) PCIE X1
- (near J7#2) CAM 2/3

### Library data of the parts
C8 C10 C12 = CMP-001-00083-2: CAP 1uF 25V ±10% case 0402(1005 metric) Thickness 1mm SMD
C9 C11 C13 = CMP-023-000006-2: CAP Standard Tantalum,  220uF, 25V, +/- 10%,  6023 (2312 inch) case, SMD
FC1-FC3 = CMP-023-000005-1: Capacitor, Filter, 1uF, 6.3V, 2A, 0603, SMD; Manufacturer_Name: Murata
IC4-IC6 = CMP-045-000045-1: Adjustable Current‐Limiting Power‐Distribution Switches, NCP380L= enable Low / H= enable high; Manufacturer_Name: onsemi; Minimum_Temperature: -40; Maximum_Temperature: +85
J3 J6 = CMP-008-000009-1: Connector; Manufacturer_Name: Molex
J4 J5 J7#1 J7#2 J8#2 = CMP-008-000016-1: Molex 501951 Series 0.5mm Pitch 22 Way SMT Female FPC Connector
J8#1 J11 = CMP-00002-2: Connector Header, GH Series, 6 Position, 1.25mm, 50V, Surface Mount, Locking Ramp, Natural; Manufacturer_Name: JST
J9 = CMP-008-000015-1: Connector; Manufacturer_Name: Hirose; Manufacturer_Part_Number: FH41-20S-0.5SH(05)
J10 = CMP-00003-2: Connector Header, GH Series, 8 Position, 1.25mm, 50V, Surface Mount, Locking Ramp, Natural; Manufacturer_Name: JST
J12 = CMP-00000-3: Connector Header, GH Series, 4 Position, 1.25mm, 50V, Surface Mount, Locking Ramp, Natural; Manufacturer_Name: JST
J13-J15 = CMP-009-000000-1: FFC & FPC Connectors 0.5 FFC For LVDS Ass ssy 15Ckt EmbsTp pkg; Manufacturer_Name: Molex
R4 = CMP-009-00181-1: RES 120R ±1% case 0603(1608 metric) Thickness 1mm SMD
R5-R7 = CMP-009-00178-2: RES 18k ±1% case 0402(1005 metric) Thickness 1mm SMD; Power Rating: 100mW

## Sheet FMU_related_Connectors.SchDoc
size A3; SheetNumber: 3; SheetTotal: 7
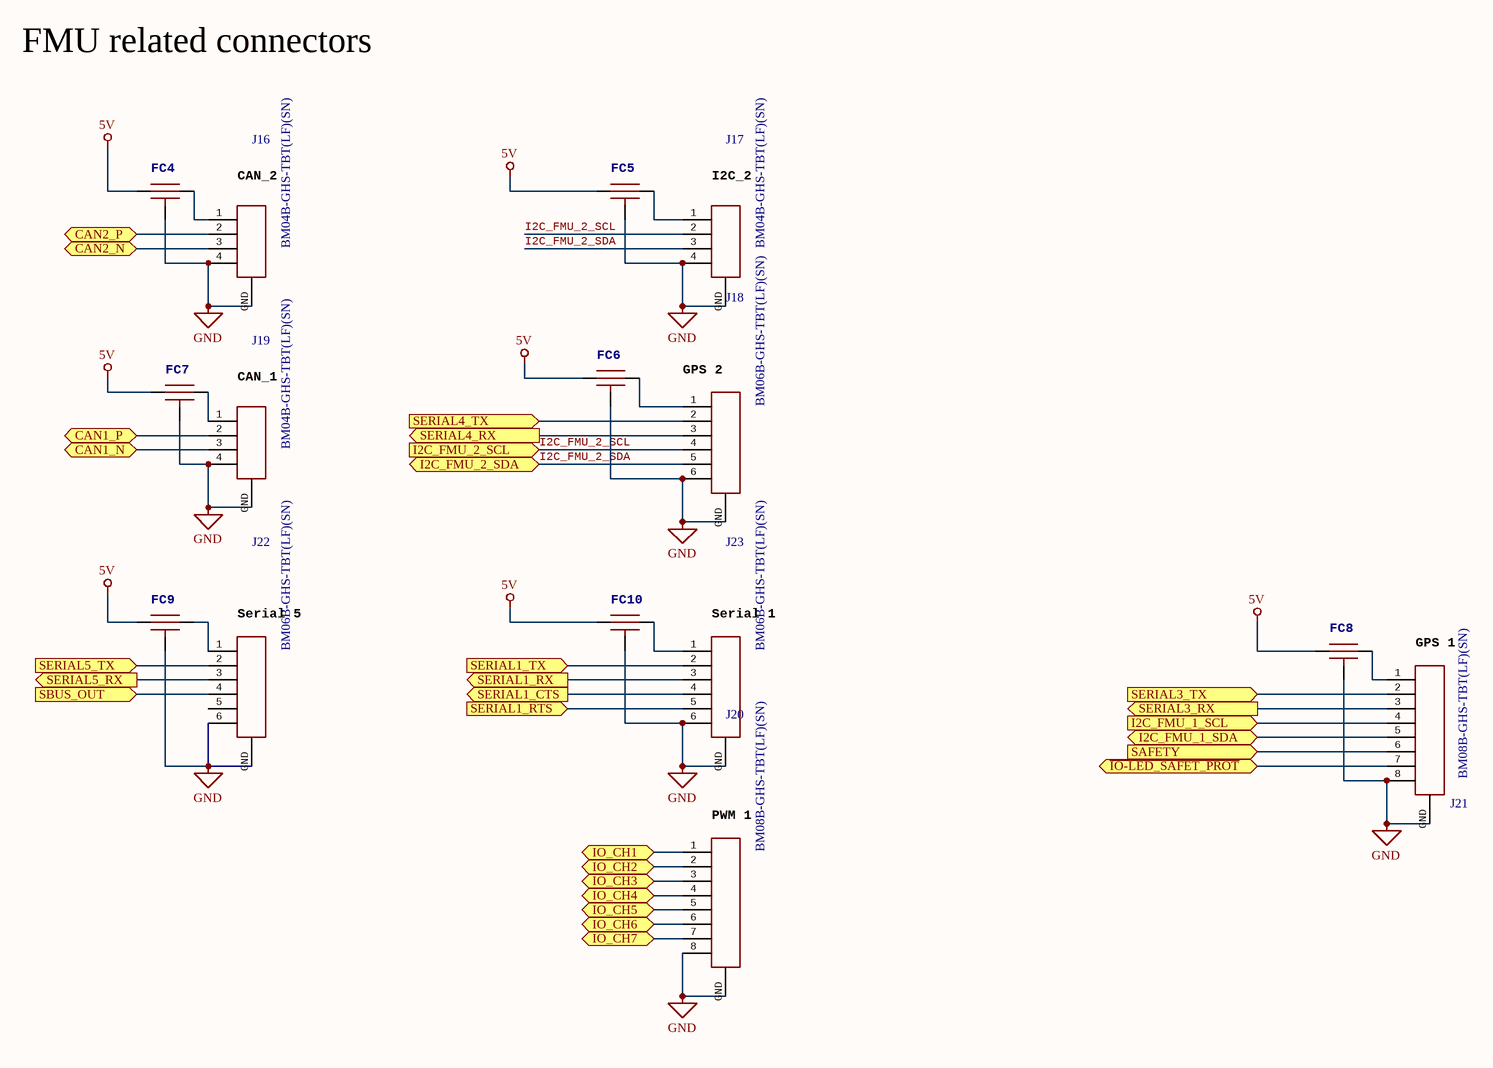
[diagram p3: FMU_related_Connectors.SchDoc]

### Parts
FC4  CMP-023-000005-1  [NFM18PS105R0J3D]  (value not drawn)
FC5  CMP-023-000005-1  [NFM18PS105R0J3D]  (value not drawn)
FC6  CMP-023-000005-1  [NFM18PS105R0J3D]  (value not drawn)
FC7  CMP-023-000005-1  [NFM18PS105R0J3D]  (value not drawn)
FC8  CMP-023-000005-1  [NFM18PS105R0J3D]  (value not drawn)
FC9  CMP-023-000005-1  [NFM18PS105R0J3D]  (value not drawn)
FC10  CMP-023-000005-1  [NFM18PS105R0J3D]  (value not drawn)
J16  BM04B-GHS-TBT(LF)(SN)  [FP-BM04B-GHS-TBT_LF_SN-MFG]
J17  BM04B-GHS-TBT(LF)(SN)  [FP-BM04B-GHS-TBT_LF_SN-MFG]
J18  BM06B-GHS-TBT(LF)(SN)  [FP-BM06B-GHS-TBT_LF_SN-MFG]
J19  BM04B-GHS-TBT(LF)(SN)  [FP-BM04B-GHS-TBT_LF_SN-MFG]
J20  BM08B-GHS-TBT(LF)(SN)  [FP-BM08B-GHS-TBT_LF_SN-MFG]
J21  BM08B-GHS-TBT(LF)(SN)  [FP-BM08B-GHS-TBT_LF_SN-MFG]
J22  BM06B-GHS-TBT(LF)(SN)  [FP-BM06B-GHS-TBT_LF_SN-MFG]
J23  BM06B-GHS-TBT(LF)(SN)  [FP-BM06B-GHS-TBT_LF_SN-MFG]

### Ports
CAN1_N (bidir), CAN1_P (bidir), CAN2_N (bidir), CAN2_P (bidir), I2C_FMU_1_SCL (in), I2C_FMU_1_SDA (bidir), I2C_FMU_2_SCL (in), I2C_FMU_2_SDA (bidir), IO_CH1 (bidir), IO_CH2 (bidir), IO_CH3 (bidir), IO_CH4 (bidir), IO_CH5 (bidir), IO_CH6 (bidir), IO_CH7 (bidir), SAFETY (in), SBUS_OUT (in), SERIAL1_CTS (out), SERIAL1_RTS (in), SERIAL1_RX (out), SERIAL1_TX (in), SERIAL3_RX (out), SERIAL3_TX (in), SERIAL4_RX (out), SERIAL4_TX (in), SERIAL5_RX (out), SERIAL5_TX (in), ~{IO-LED_SAFET_PROT} (bidir)

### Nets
5V: FC4.1 FC5.1 FC6.1 FC7.1 FC8.1 FC9.1 FC10.1
GND: FC4.GND FC5.GND FC6.GND FC7.GND FC8.GND FC9.GND FC10.GND J16.4 J16.GND J17.4 J17.GND J18.6 J18.GND J19.4 J19.GND J20.8 J20.GND J21.8 J21.GND J22.6 J22.GND J23.6 J23.GND
CAN_1_N: J19.3 ; port CAN1_N
CAN_1_P: J19.2 ; port CAN1_P
CAN_2_N: J16.3 ; port CAN2_N
CAN_2_P: J16.2 ; port CAN2_P
FMU_SAFETY_SIG: J21.6 ; port SAFETY
I2C_FMU_1_SCL: J21.4 ; port I2C_FMU_1_SCL
I2C_FMU_1_SDA: J21.5 ; port I2C_FMU_1_SDA
I2C_FMU_2_SCL: J17.2 J18.4 ; port I2C_FMU_2_SCL
I2C_FMU_2_SDA: J17.3 J18.5 ; port I2C_FMU_2_SDA
~{IO-LED_SAFET_PROT}: J21.7 ; port ~{IO-LED_SAFET_PROT}
IO_CH1: J20.1 ; port IO_CH1
IO_CH2: J20.2 ; port IO_CH2
IO_CH3: J20.3 ; port IO_CH3
IO_CH4: J20.4 ; port IO_CH4
IO_CH5: J20.5 ; port IO_CH5
IO_CH6: J20.6 ; port IO_CH6
IO_CH7: J20.7 ; port IO_CH7
SBUS_OUT: J22.4 ; port SBUS_OUT
SERIAL1_CTS: J23.4 ; port SERIAL1_CTS
SERIAL1_RTS: J23.5 ; port SERIAL1_RTS
SERIAL1_RX: J23.3 ; port SERIAL1_RX
SERIAL1_TX: J23.2 ; port SERIAL1_TX
SERIAL3_RX: J21.3 ; port SERIAL3_RX
SERIAL3_TX: J21.2 ; port SERIAL3_TX
SERIAL4_RX: J18.3 ; port SERIAL4_RX
SERIAL4_TX: J18.2 ; port SERIAL4_TX
SERIAL5_RX: J22.3 ; port SERIAL5_RX
SERIAL5_TX: J22.2 ; port SERIAL5_TX
NetFC4_2: FC4.2 J16.1
NetFC5_2: FC5.2 J17.1
NetFC6_2: FC6.2 J18.1
NetFC7_2: FC7.2 J19.1
NetFC8_2: FC8.2 J21.1
NetFC9_2: FC9.2 J22.1
NetFC10_2: FC10.2 J23.1

Not connected (* = marked no-connect by the designer): J22 5

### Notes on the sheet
- FMU related connectors
- CAN_2
- (near J17) I2C_2
- CAN_1
- (near J18) GPS 2
- (near J22) Serial 5
- (near J23) Serial 1
- (near J21) GPS 1
- (near J20) PWM 1

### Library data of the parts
FC4-FC10 = CMP-023-000005-1: as FC1 on sheet Jetson_Connectors
J16 J17 J19 = CMP-00000-3: as J12 on sheet Jetson_Connectors
J18 J22 J23 = CMP-00002-2: as J8#1 on sheet Jetson_Connectors
J20 J21 = CMP-00003-2: as J10 on sheet Jetson_Connectors

## Sheet PDB_Related_Connectors.SchDoc
size A3; SheetNumber: 5; SheetTotal: 7
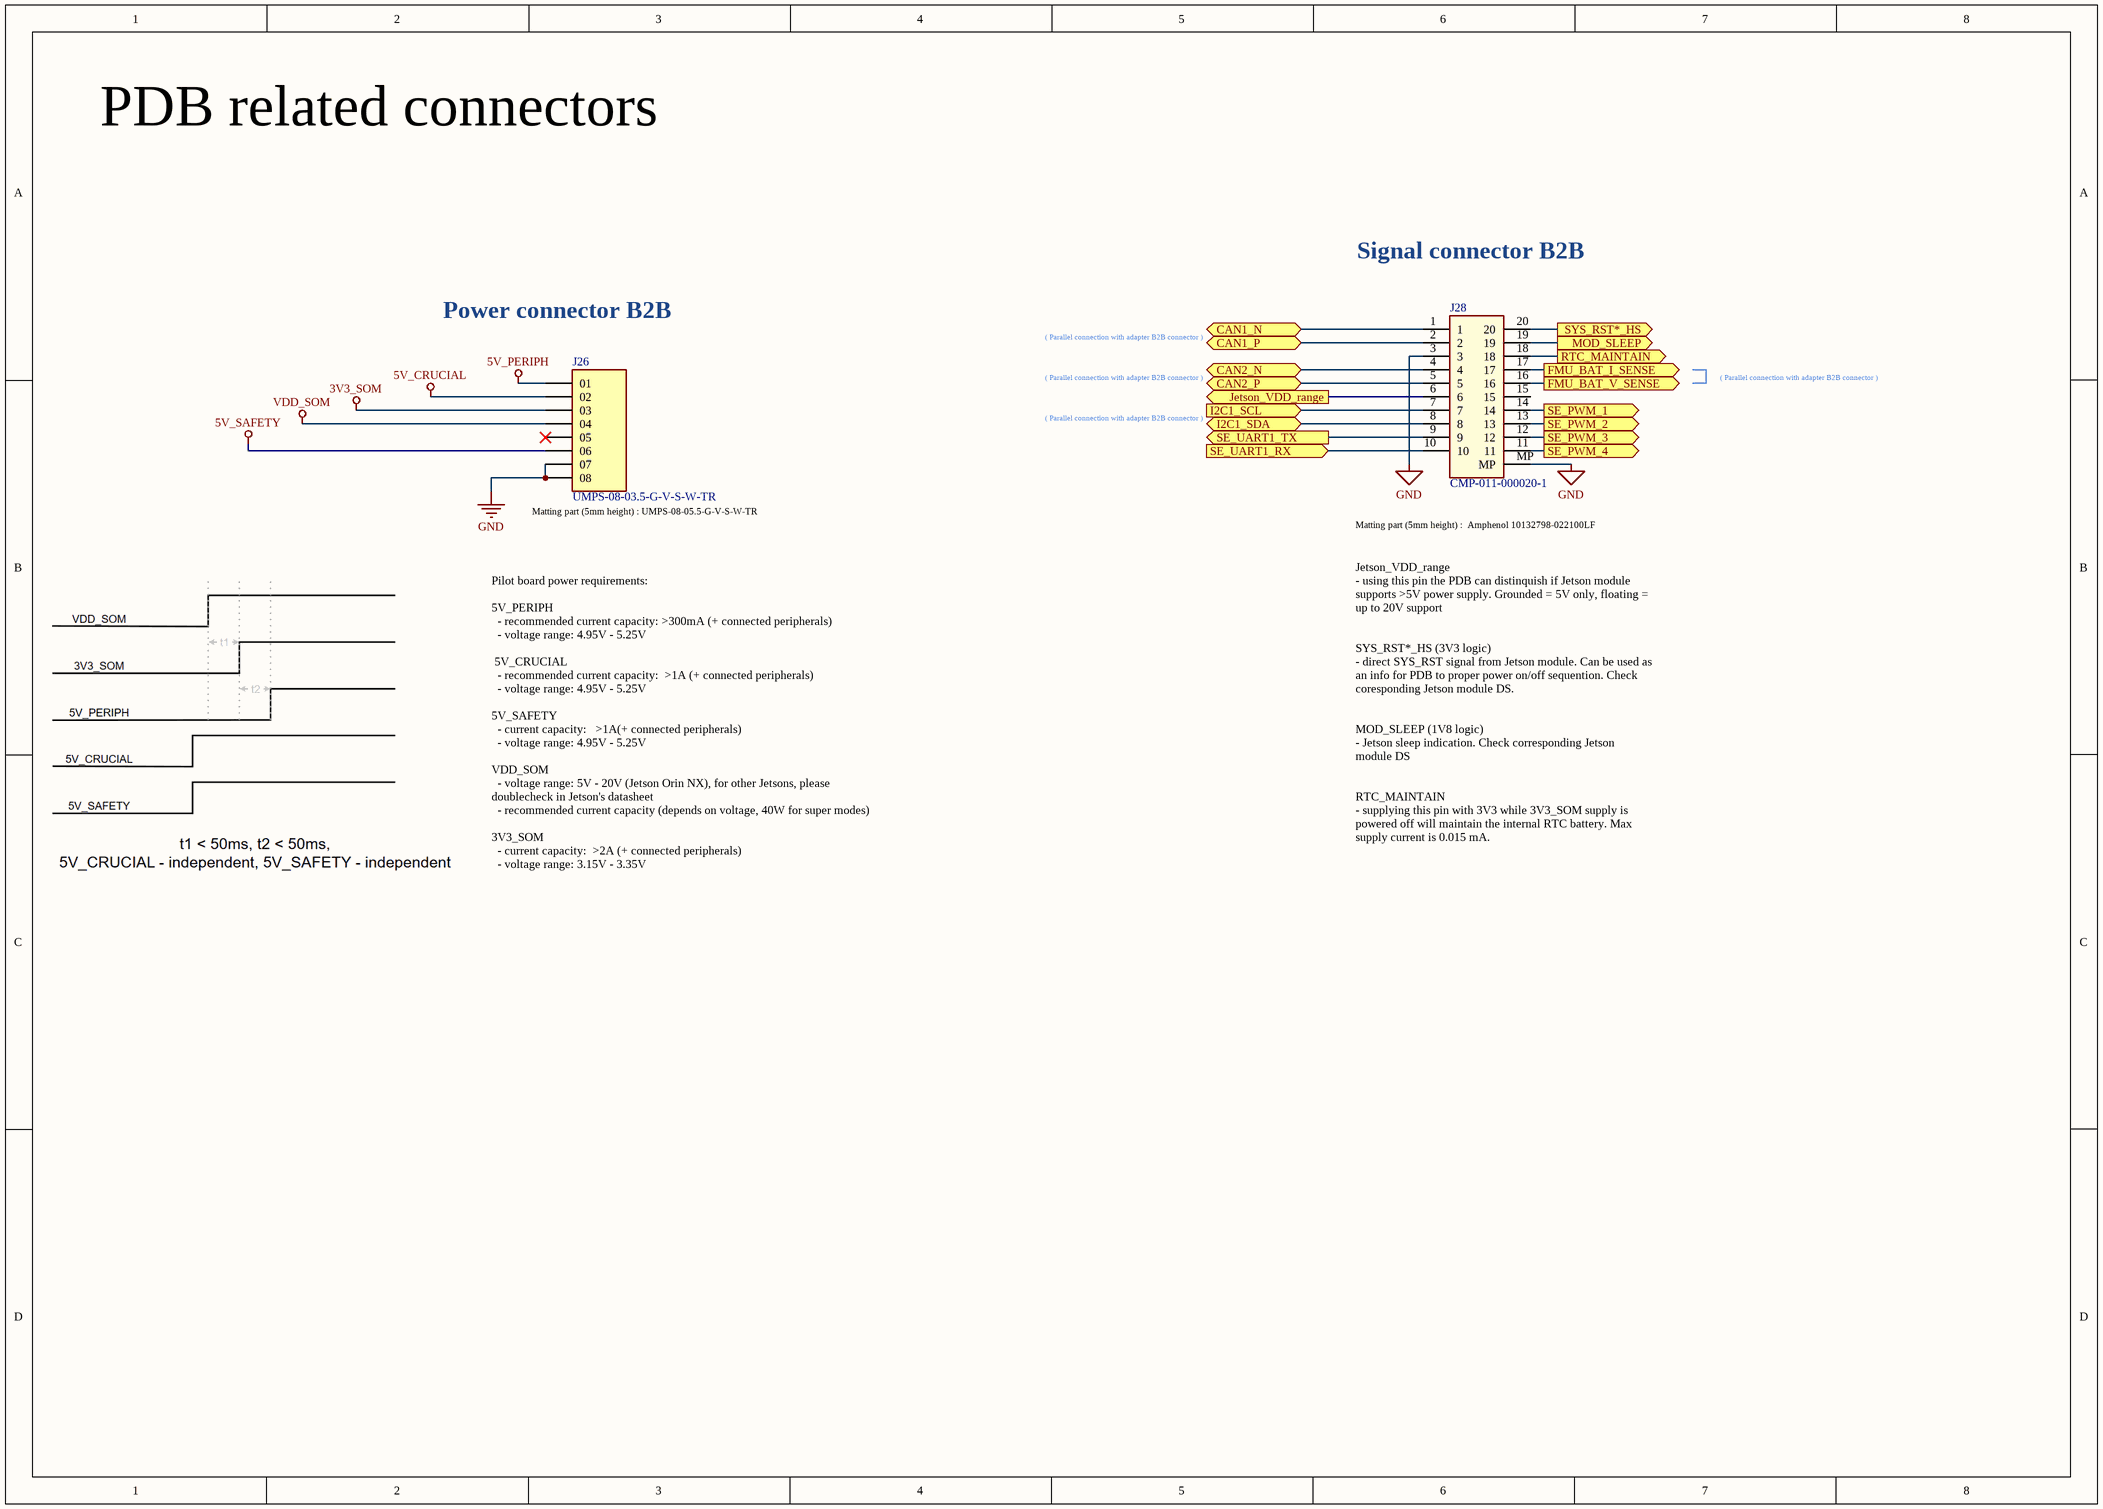
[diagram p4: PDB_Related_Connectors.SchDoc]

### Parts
J26  UMPS-08-03.5-G-V-S-W-TR  [SAMTEC_UMPS-08-03.5-G-V-S-W-TR]
J28  CMP-011-000020-1  [10132797-025100LF]

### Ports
CAN1_N (bidir), CAN1_P (bidir), CAN2_N (bidir), CAN2_P (bidir), FMU_BAT_I_SENSE (out), FMU_BAT_V_SENSE (out), I2C1_SCL (in), I2C1_SDA (bidir), Jetson_VDD_range (out), MOD_SLEEP (out), RTC_MAINTAIN (out), SE_PWM_1 (out), SE_PWM_2 (out), SE_PWM_3 (out), SE_PWM_4 (out), SE_UART1_RX (in), SE_UART1_TX (out), SYS_RST*_HS (out)

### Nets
3V3_SOM: J26.03
5V_CRUCIAL: J26.02
5V_PERIPH: J26.01
5V_SAFETY: J26.06
GND: J26.07 J26.08 J28.3 J28.MP
VDD_SOM: J26.04
NetJ28_1: J28.1 ; port CAN1_N
NetJ28_2: J28.2 ; port CAN1_P
NetJ28_4: J28.4 ; port CAN2_N
NetJ28_5: J28.5 ; port CAN2_P
NetJ28_6: J28.6 ; port Jetson_VDD_range
NetJ28_7: J28.7 ; port I2C1_SCL
NetJ28_8: J28.8 ; port I2C1_SDA
NetJ28_9: J28.9 ; port SE_UART1_TX
NetJ28_10: J28.10 ; port SE_UART1_RX
NetJ28_11: J28.11 ; port SE_PWM_4
NetJ28_12: J28.12 ; port SE_PWM_3
NetJ28_13: J28.13 ; port SE_PWM_2
NetJ28_14: J28.14 ; port SE_PWM_1
NetJ28_16: J28.16 ; port FMU_BAT_V_SENSE
NetJ28_17: J28.17 ; port FMU_BAT_I_SENSE
NetJ28_18: J28.18 ; port RTC_MAINTAIN
NetJ28_19: J28.19 ; port MOD_SLEEP
NetJ28_20: J28.20 ; port SYS_RST*_HS

Not connected (* = marked no-connect by the designer): J26 05*; J28 15

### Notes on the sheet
- PDB related connectors
- Signal connector B2B
- Power connector B2B
- ( Parallel connection with adapter B2B connector )
- (near J26) Matting part (5mm height) : UMPS-08-05.5-G-V-S-W-TR
- Matting part (5mm height) :  Amphenol 10132798-022100LF
- Pilot board power requirements:
  5V_PERIPH
  - recommended current capacity: >300mA (+ connected peripherals)
  - voltage range: 4.95V - 5.25V
  5V_CRUCIAL
  - recommended current capacity:  >1A (+ connected peripherals)
  - voltage range: 4.95V - 5.25V
  5V_SAFETY
  - current capacity:   >1A(+ connected peripherals)
  - voltage range: 4.95V - 5.25V
  VDD_SOM
  - voltage range: 5V - 20V (Jetson Orin NX), for other Jetsons, please doublecheck in Jetson's datasheet
  - recommended current capacity (depends on voltage, 40W for super modes)
  3V3_SOM
  - current capacity:  >2A (+ connected peripherals)
  - voltage range: 3.15V - 3.35V
- Jetson_VDD_range
  - using this pin the PDB can distinquish if Jetson module supports >5V power supply. Grounded = 5V only, floating = up to 20V support
  SYS_RST*_HS (3V3 logic)
  - direct SYS_RST signal from Jetson module. Can be used as an info for PDB to proper power on/off sequention. Check coresponding Jetson module DS.
  MOD_SLEEP (1V8 logic)
  - Jetson sleep indication. Check corresponding Jetson module DS
  RTC_MAINTAIN
  - supplying this pin with 3V3 while 3V3_SOM supply is powered off will maintain the internal RTC battery. Max supply current is 0.015 mA.

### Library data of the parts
J26 = CMP-013-000042-1: Power to the Board; Manufacturer_Name: Samtec
J28 = CMP-011-000020-1: BergStak® 0.5mm Mezzanine Connector; Manufacturer_Name: Amphenol

## Sheet Current_limiters.SchDoc
size A4; SheetNumber: 6; SheetTotal: 9
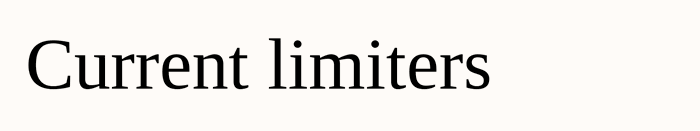
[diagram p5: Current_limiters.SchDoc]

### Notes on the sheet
- Current limiters

## Sheet DCDC_Regulators.SchDoc
size A3; SheetNumber: 7; SheetTotal: 9
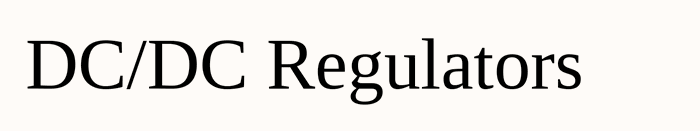
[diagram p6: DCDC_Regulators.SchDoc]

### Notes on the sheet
- DC/DC Regulators

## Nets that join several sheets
5V: Jetson_Connectors (13 pins), FMU_related_Connectors (7 pins)
GND: Adapter_B2B_Connectors (84 pins), Jetson_Connectors (107 pins), FMU_related_Connectors (23 pins), PDB_Related_Connectors (J26.07 J26.08 J28.3 J28.MP)
CAM_I2C_SCL: Adapter_B2B_Connectors (J1.29), Jetson_Connectors (J4.3)
CAM_I2C_SDA: Adapter_B2B_Connectors (J1.31), Jetson_Connectors (J4.2)
CAN_1_N: Adapter_B2B_Connectors (J2.51), FMU_related_Connectors (J19.3)
CAN_1_P: Adapter_B2B_Connectors (J2.53), FMU_related_Connectors (J19.2)
CAN_2_N: Adapter_B2B_Connectors (J2.47), FMU_related_Connectors (J16.3)
CAN_2_P: Adapter_B2B_Connectors (J2.49), FMU_related_Connectors (J16.2)
CAN_JET_N: Adapter_B2B_Connectors (J2.43), Jetson_Connectors (J12.3 R4.1)
CAN_JET_P: Adapter_B2B_Connectors (J2.41), Jetson_Connectors (J12.2 R4.2)
CS0: Adapter_B2B_Connectors (J1.13), Jetson_Connectors (J10.3)
CS1: Adapter_B2B_Connectors (J1.15), Jetson_Connectors (J10.2)
CSI0_CLK_N: Adapter_B2B_Connectors (J1.108), Jetson_Connectors (J4.15)
CSI0_CLK_P: Adapter_B2B_Connectors (J1.106), Jetson_Connectors (J4.14)
CSI0_D0_N: Adapter_B2B_Connectors (J1.116), Jetson_Connectors (J4.21)
CSI0_D0_P: Adapter_B2B_Connectors (J1.114), Jetson_Connectors (J4.20)
CSI0_D1_N: Adapter_B2B_Connectors (J1.102), Jetson_Connectors (J4.18)
CSI0_D1_P: Adapter_B2B_Connectors (J1.100), Jetson_Connectors (J4.17)
CSI1_CLK_N: Adapter_B2B_Connectors (J1.107), Jetson_Connectors (J5.15)
CSI1_CLK_P: Adapter_B2B_Connectors (J1.105), Jetson_Connectors (J5.14)
CSI1_D0_N: Adapter_B2B_Connectors (J1.115), Jetson_Connectors (J5.21)
CSI1_D0_P: Adapter_B2B_Connectors (J1.113), Jetson_Connectors (J5.20)
CSI1_D1_N: Adapter_B2B_Connectors (J1.101), Jetson_Connectors (J5.18)
CSI1_D1_P: Adapter_B2B_Connectors (J1.99), Jetson_Connectors (J5.17)
CSI2_CLK_N: Adapter_B2B_Connectors (J1.88), Jetson_Connectors (J7#2.15)
CSI2_CLK_P: Adapter_B2B_Connectors (J1.86), Jetson_Connectors (J7#2.14)
CSI2_D0_N: Adapter_B2B_Connectors (J1.96), Jetson_Connectors (J7#2.21)
CSI2_D0_P: Adapter_B2B_Connectors (J1.94), Jetson_Connectors (J7#2.20)
CSI2_D1_N: Adapter_B2B_Connectors (J1.82), Jetson_Connectors (J7#2.18)
CSI2_D1_P: Adapter_B2B_Connectors (J1.80), Jetson_Connectors (J7#2.17)
CSI3_D0_N: Adapter_B2B_Connectors (J1.95), Jetson_Connectors (J7#2.12)
CSI3_D0_P: Adapter_B2B_Connectors (J1.93), Jetson_Connectors (J7#2.11)
CSI3_D1_N: Adapter_B2B_Connectors (J1.81), Jetson_Connectors (J7#2.9)
CSI3_D1_P: Adapter_B2B_Connectors (J1.79), Jetson_Connectors (J7#2.8)
ETH1A_N: Adapter_B2B_Connectors (J2.89), Jetson_Connectors (J3.11)
ETH1A_P: Adapter_B2B_Connectors (J2.85), Jetson_Connectors (J3.10)
ETH1B_N: Adapter_B2B_Connectors (J2.99), Jetson_Connectors (J3.8)
ETH1B_P: Adapter_B2B_Connectors (J2.95), Jetson_Connectors (J3.7)
ETH1C_N: Adapter_B2B_Connectors (J2.107), Jetson_Connectors (J3.5)
ETH1C_P: Adapter_B2B_Connectors (J2.103), Jetson_Connectors (J3.4)
ETH1D_N: Adapter_B2B_Connectors (J2.117), Jetson_Connectors (J3.2)
ETH1D_P: Adapter_B2B_Connectors (J2.113), Jetson_Connectors (J3.1)
ETH2A_N: Adapter_B2B_Connectors (J2.90), Jetson_Connectors (J6.11)
ETH2A_P: Adapter_B2B_Connectors (J2.86), Jetson_Connectors (J6.10)
ETH2B_N: Adapter_B2B_Connectors (J2.100), Jetson_Connectors (J6.8)
ETH2B_P: Adapter_B2B_Connectors (J2.96), Jetson_Connectors (J6.7)
ETH2C_N: Adapter_B2B_Connectors (J2.108), Jetson_Connectors (J6.5)
ETH2C_P: Adapter_B2B_Connectors (J2.104), Jetson_Connectors (J6.4)
ETH2D_N: Adapter_B2B_Connectors (J2.118), Jetson_Connectors (J6.2)
ETH2D_P: Adapter_B2B_Connectors (J2.114), Jetson_Connectors (J6.1)
FMU_BAT_I_SENSE: Adapter_B2B_Connectors (J2.27), Jetson_Connectors (J8#1.4)
FMU_BAT_V_SENSE: Adapter_B2B_Connectors (J2.25), Jetson_Connectors (J8#1.3)
FMU_SAFETY_SIG: Adapter_B2B_Connectors (J2.70), FMU_related_Connectors (J21.6)
GPIO_EXP_0: Adapter_B2B_Connectors (J2.29), Jetson_Connectors (J4.6)
GPIO_EXP_1: Adapter_B2B_Connectors (J2.31), Jetson_Connectors (J5.6)
GPIO_EXP_2: Adapter_B2B_Connectors (J2.33), Jetson_Connectors (J7#2.6)
GPIO_EXP_4: Adapter_B2B_Connectors (J2.37), Jetson_Connectors (J8#1.1)
GPIO_EXP_5: Adapter_B2B_Connectors (J2.39), Jetson_Connectors (J8#1.2)
I2C0_SCL: Adapter_B2B_Connectors (J1.33), Jetson_Connectors (J5.3 J11.4)
I2C0_SDA: Adapter_B2B_Connectors (J1.35), Jetson_Connectors (J5.2 J11.5)
I2C1_SCL: Adapter_B2B_Connectors (J1.37), Jetson_Connectors (J7#2.3)
I2C1_SDA: Adapter_B2B_Connectors (J1.39), Jetson_Connectors (J7#2.2)
I2C_FMU_1_SCL: Adapter_B2B_Connectors (J2.78), FMU_related_Connectors (J21.4)
I2C_FMU_1_SDA: Adapter_B2B_Connectors (J2.80), FMU_related_Connectors (J21.5)
I2C_FMU_2_SCL: Adapter_B2B_Connectors (J2.82), FMU_related_Connectors (J17.2 J18.4)
I2C_FMU_2_SDA: Adapter_B2B_Connectors (J2.84), FMU_related_Connectors (J17.3 J18.5)
~{IO-LED_SAFET_PROT}: Adapter_B2B_Connectors (J2.74), FMU_related_Connectors (J21.7)
IO_CH1: Adapter_B2B_Connectors (J2.68), FMU_related_Connectors (J20.1)
IO_CH2: Adapter_B2B_Connectors (J2.66), FMU_related_Connectors (J20.2)
IO_CH3: Adapter_B2B_Connectors (J2.64), FMU_related_Connectors (J20.3)
IO_CH4: Adapter_B2B_Connectors (J2.62), FMU_related_Connectors (J20.4)
IO_CH5: Adapter_B2B_Connectors (J2.60), FMU_related_Connectors (J20.5)
IO_CH6: Adapter_B2B_Connectors (J2.58), FMU_related_Connectors (J20.6)
IO_CH7: Adapter_B2B_Connectors (J2.56), FMU_related_Connectors (J20.7)
JET_PWM_OUT_1: Adapter_B2B_Connectors (J1.71), Jetson_Connectors (J4.5 J5.5 J7#2.5)
MISO: Adapter_B2B_Connectors (J1.11), Jetson_Connectors (J10.4)
MOSI: Adapter_B2B_Connectors (J1.7), Jetson_Connectors (J10.6)
nPCIE_CLKREQ: Adapter_B2B_Connectors (J1.45), Jetson_Connectors (J9.14)
nPCIE_RST: Adapter_B2B_Connectors (J1.47), Jetson_Connectors (J9.13)
nPCIE_WAKE: Adapter_B2B_Connectors (J1.49), Jetson_Connectors (J9.15)
PCIE_AD_CLK_N: Adapter_B2B_Connectors (J1.55), Jetson_Connectors (J9.9)
PCIE_AD_CLK_P: Adapter_B2B_Connectors (J1.53), Jetson_Connectors (J9.8)
PCIE_AD_RX_N: Adapter_B2B_Connectors (J1.67), Jetson_Connectors (J9.6)
PCIE_AD_RX_P: Adapter_B2B_Connectors (J1.65), Jetson_Connectors (J9.5)
PCIE_AD_TX_N: Adapter_B2B_Connectors (J1.61), Jetson_Connectors (J9.3)
PCIE_AD_TX_P: Adapter_B2B_Connectors (J1.59), Jetson_Connectors (J9.2)
SBUS_OUT: Adapter_B2B_Connectors (J2.72), FMU_related_Connectors (J22.4)
SCK: Adapter_B2B_Connectors (J1.9), Jetson_Connectors (J10.5)
SERIAL1_CTS: Adapter_B2B_Connectors (J2.79), FMU_related_Connectors (J23.4)
SERIAL1_RTS: Adapter_B2B_Connectors (J2.77), FMU_related_Connectors (J23.5)
SERIAL1_RX: Adapter_B2B_Connectors (J2.73), FMU_related_Connectors (J23.3)
SERIAL1_TX: Adapter_B2B_Connectors (J2.75), FMU_related_Connectors (J23.2)
SERIAL3_RX: Adapter_B2B_Connectors (J2.63), FMU_related_Connectors (J21.3)
SERIAL3_TX: Adapter_B2B_Connectors (J2.61), FMU_related_Connectors (J21.2)
SERIAL4_RX: Adapter_B2B_Connectors (J2.67), FMU_related_Connectors (J18.3)
SERIAL4_TX: Adapter_B2B_Connectors (J2.65), FMU_related_Connectors (J18.2)
SERIAL5_RX: Adapter_B2B_Connectors (J2.71), FMU_related_Connectors (J22.3)
SERIAL5_TX: Adapter_B2B_Connectors (J2.69), FMU_related_Connectors (J22.2)
UART_JET_RX: Adapter_B2B_Connectors (J1.27), Jetson_Connectors (J11.3)
UART_JET_TX: Adapter_B2B_Connectors (J1.25), Jetson_Connectors (J11.2)
USB_0_N: Adapter_B2B_Connectors (J1.18), Jetson_Connectors (J13.8)
USB_0_OCS: Adapter_B2B_Connectors (J1.10), Jetson_Connectors (IC4.3)
USB_0_P: Adapter_B2B_Connectors (J1.16), Jetson_Connectors (J13.9)
USB_0_PWR: Adapter_B2B_Connectors (J1.12), Jetson_Connectors (IC4.4)
USB_1_N: Adapter_B2B_Connectors (J1.64), Jetson_Connectors (J14.8)
USB_1_OCS: Adapter_B2B_Connectors (J1.56), Jetson_Connectors (IC5.3)
USB_1_P: Adapter_B2B_Connectors (J1.62), Jetson_Connectors (J14.9)
USB_1_PWR: Adapter_B2B_Connectors (J1.58), Jetson_Connectors (IC5.4)
USB_2_N: Adapter_B2B_Connectors (J1.48), Jetson_Connectors (J15.8)
USB_2_OCS: Adapter_B2B_Connectors (J1.52), Jetson_Connectors (9 pins)
USB_2_P: Adapter_B2B_Connectors (J1.46), Jetson_Connectors (J15.9)
USB_2_PWR: Adapter_B2B_Connectors (J1.54), Jetson_Connectors (IC6.4)
USBSS0_RX_N: Adapter_B2B_Connectors (J1.30), Jetson_Connectors (J13.2)
USBSS0_RX_P: Adapter_B2B_Connectors (J1.28), Jetson_Connectors (J13.3)
USBSS0_TX_N: Adapter_B2B_Connectors (J1.24), Jetson_Connectors (J13.5)
USBSS0_TX_P: Adapter_B2B_Connectors (J1.22), Jetson_Connectors (J13.6)
USBSS1_RX_N: Adapter_B2B_Connectors (J1.76), Jetson_Connectors (J14.2)
USBSS1_RX_P: Adapter_B2B_Connectors (J1.74), Jetson_Connectors (J14.3)
USBSS1_TX_N: Adapter_B2B_Connectors (J1.70), Jetson_Connectors (J14.5)
USBSS1_TX_P: Adapter_B2B_Connectors (J1.68), Jetson_Connectors (J14.6)
USBSS2_RX_N: Adapter_B2B_Connectors (J1.42), Jetson_Connectors (J15.2)
USBSS2_RX_P: Adapter_B2B_Connectors (J1.40), Jetson_Connectors (J15.3)
USBSS2_TX_N: Adapter_B2B_Connectors (J1.36), Jetson_Connectors (J15.5)
USBSS2_TX_P: Adapter_B2B_Connectors (J1.34), Jetson_Connectors (J15.6)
